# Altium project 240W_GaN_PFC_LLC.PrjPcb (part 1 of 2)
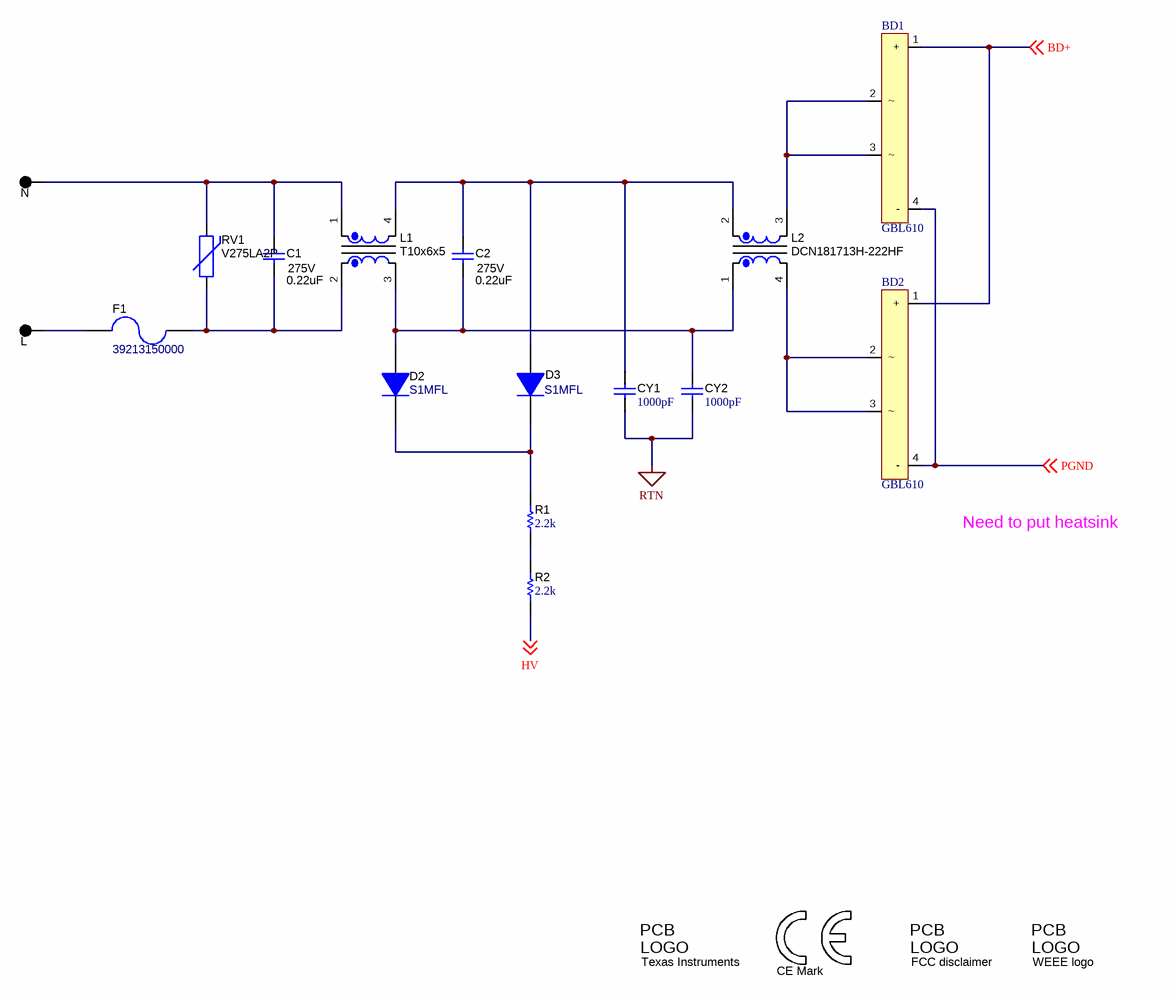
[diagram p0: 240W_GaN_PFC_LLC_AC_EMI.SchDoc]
CopyrightYear: 2024; PCB_Layout: M. Huang; PCB_Rev: E1; PRJ_Engineer: M. Huang / J. Gomez; PRJ_Number: 240W PFC + LLC; PRJ_Title: 240W PFC + LLC; SCH_Rev: E1; TechSupport: http://www.ti.com/support; TID: N/A
3 sheets, 163 parts. Net scope: global (net labels, ports and power ports of the same name join across sheets).
Board file: 240W_GaN_PFC_LLC.PcbDoc
Sheets:
  240W_GaN_PFC_LLC_AC_EMI.SchDoc
  240W_LLC_Stage.SchDoc
  240W_PFC_Stage.SchDoc

## Sheet 240W_GaN_PFC_LLC_AC_EMI.SchDoc
size 431 x 279 mm; Date: Not shown in title block; ApprovedBy: Not shown in title block; CheckedBy: Not shown in title block; Author: Not shown in title block; CompanyName: Not shown in title block; Engineer: Not shown in title block; Organization: Not shown in title block; Address1: Not shown in title block; Address2: Not shown in title block; Address3: Not shown in title block; Address4: Not shown in title block; DocumentNumber: 3; Revision: Use project parameter SCH_Rev; SheetNumber: 1; SheetTotal: 2; PageSetup: Record=PageOptions¦CenterHorizontal=True¦CenterVertical=True¦PrintScale=1.00¦XCorrection=1.00¦YCorrection=1.00¦PrintKind=0¦BorderSize=5000000¦LeftOffset=0¦BottomOffset=0¦Orientation=2¦PaperLength=1000¦PaperWidth=1000¦Scale=100¦PaperSource=15¦PrintQuality=600¦MediaType=1¦DitherType=10¦PaperKind=Letter¦PrintScaleMode=1

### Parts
BD1  GBL610  [GBL610]
BD2  GBL610  [GBL610]
C1  VDC_V: 275V  ValueDisplayed: 0.22uF  [WCAP-FTX2_1500x700x1250]  (hidden comment: 890324024002)
C2  VDC_V: 275V  ValueDisplayed: 0.22uF  [WCAP-FTX2_1500x700x1250]  (hidden comment: 890324024002)
CY1  ValueDisplayed: 1000pF  [DK1_86]  (hidden comment: DK1E3EA102M86RAH01)
CY2  ValueDisplayed: 1000pF  [DK1_86]  (hidden comment: DK1E3EA102M86RAH01)
D2  S1MFL  [SOD-123]
D3  S1MFL  [SOD-123]
F1  39213150000  [FUSE_392]
L1  T10x6x5  [T10x6x5]
L2  DCN181713H-222HF  [CM_DCN181713H]
Logo1  CE Mark  [CE_Mark_5mm]  (no BOM)
Logo2  Texas Instruments  [TI_Stacked_Overlay_Small]  (no BOM)
Logo3  FCC disclaimer  [FCC_disclaimer]  (no BOM)
Logo4  WEEE logo  [WEEE_Minimum]  (no BOM)
R1  ValueDisplayed: 2.2k  [1206]  (hidden comment: CRCW12062K20JNEA)
R2  ValueDisplayed: 2.2k  [1206]  (hidden comment: CRCW12062K20JNEA)
RV1  V275LA2P  [Littelfuse_V275LA_7MM]
TP1  N  [Keystone5011]
TP2  L  [Keystone5011]

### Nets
PGND: BD1.4(-) BD2.4(-) ; off-sheet PGND
RTN: CY1.2 CY2.2
BD+: BD1.1(+) BD2.1(+) ; off-sheet BD+
HV: R2.1 ; off-sheet HV
NetBD1_2: BD1.2 BD1.3 L2.3
NetBD2_2: BD2.2 BD2.3 L2.4
NetC1_1: C1.1 L1.1 RV1.2 TP1.1
NetC1_2: C1.2 F1.1 L1.2 RV1.1
NetC2_1: C2.1 CY1.1 D3.2(A) L1.4 L2.2
NetC2_2: C2.2 CY2.1 D2.2(A) L1.3 L2.1
NetD2_1: D2.1(K) D3.1(K) R1.2
NetF1_2: F1.2 TP2.1
NetR1_1: R1.1 R2.2

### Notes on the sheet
- Need to put heatsink

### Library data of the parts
BD1 BD2 = BD
C1 C2 = CMP-0012312-3: CAP, Film, 0.22 uF, 275 V, +/- 10%, TH; Manufacturer: Wurth Elektronik; TaMin_C: -40°C; Polarized: N; SizeAreaWB_mm2: 153; Value1: Unknown; Value: 0.22uF; TaMax_C: 105°C; SizeZ_mm: 13; SizeX_mm: 15; SizeY_mm: 7; Cap_Case: 15x7x12.5; SizeArea_mm2: 105; Cap_F: 220nF; AEC Category: Q200
CY1 CY2 = CMP-0077997-1: CAP, CERM, 1000 pF, X1 440 VAC/Y1 250 VAC, +/- 20%, E, 8x6mm; Manufacturer: MuRata; Cap_F: 1nF; VAC_X: 440; SizeAreaWB_mm2: 107.2; VAC_Y: 250; SizeArea_mm2: 68.4; AEC Qualified: N; AEC Category: Q200; Value: 1000pF; TaMax_C: 125°C; SizeZ_mm: 2.5; TaMin_C: -40°C; SizeY_mm: 6; U/M: EA; AC_Safety: X1Y1; SizeX_mm: 11.4
D2 D3 = CMP-0029032-2: Diode, GP, 1KV, 1 A, SOD-123F; Manufacturer: ON Semiconductor; Value: 1000V; Type: Switching; SizeY_mm: 1.7; Io_A: 1A; SizeAreaWB_mm2: 13.095; SizeArea_mm2: 6.545; Vf_V: 1V; TJmax_C: 150°C; SizeX_mm: 3.85; SizeZ_mm: 1.35; Green_Lifecycle: Active; Green_REACh: Passed
F1 = CMP-0003561-2: Fuse, 3.15 A, 250VAC/VDC, TH; Manufacturer: Littelfuse; Irating_A: 3.15A; VAC_V: 250V
L1 L2 = CM_Choke_Planar: Manufacturer: Used in BOM report; CompType: Used in some BOM reports.  Useful for finding later.
Logo1 = CMP-0074844-1: SymbolCreator: a0412235
Logo2 = CMP-0074838-1: Texas Instrument Corporate Signature; SymbolCreator: a0412235; Lib Reference: TI_Logo; Library Reference: Logo
Logo3 = CMP-0074847-1: FCC_disclaimer; Library Reference: Logo
Logo4 = CMP-0074769-1
R1 R2 = CMP-0018641-3: RES, 2.2 k, 5%, 0.25 W, AEC-Q200 Grade 0, 1206; Manufacturer: Vishay-Dale; Power_W: 250mW; TempCo: 200 ppm/C; Value_Code: 2k20; Value: 2.2k; EIA_Code: E24; SizeX_mm: 3.2; SizeY_mm: 1.6; SizeZ_mm: 1.35; Value2: 0.25W; SizeArea_mm2: 5.12; AEC Qualified: Y; VDC_V: 200V; AEC Category: Q200; AEC Grade: 0
RV1 = CMP-0001908-4: VARISTOR 450V 1.2KA DISC 7MM; Manufacturer: Littelfuse; SizeX_mm: 7; SizeArea_mm2: 39.2; SizeY_mm: 5.6; SizeAreaWB_mm2: 68.4; SizeZ_mm: 12
TP1 TP2 = CMP-0055148-1: Test Point, Multipurpose, Black, TH; Manufacturer: Keystone; CNHeader: FALSE; Green_Lifecycle: Active; Green_REACh: Passed; ContactFinish: Silver; CT: TRUE

## Sheet 240W_LLC_Stage.SchDoc
size 431 x 279 mm; Date: Not shown in title block; ApprovedBy: Not shown in title block; CheckedBy: Not shown in title block; Author: Not shown in title block; CompanyName: Not shown in title block; Engineer: Not shown in title block; Organization: Not shown in title block; Address1: Not shown in title block; Address2: Not shown in title block; Address3: Not shown in title block; Address4: Not shown in title block; DocumentNumber: 2; Revision: Use project parameter SCH_Rev; SheetNumber: 2; SheetTotal: 3; PageSetup: Record=PageOptions¦CenterHorizontal=True¦CenterVertical=True¦PrintScale=1.00¦XCorrection=1.00¦YCorrection=1.00¦PrintKind=0¦BorderSize=5000000¦LeftOffset=0¦BottomOffset=0¦Orientation=2¦PaperLength=1000¦PaperWidth=1000¦Scale=100¦PaperSource=15¦PrintQuality=600¦MediaType=1¦DitherType=10¦PaperKind=Letter¦PrintScaleMode=1
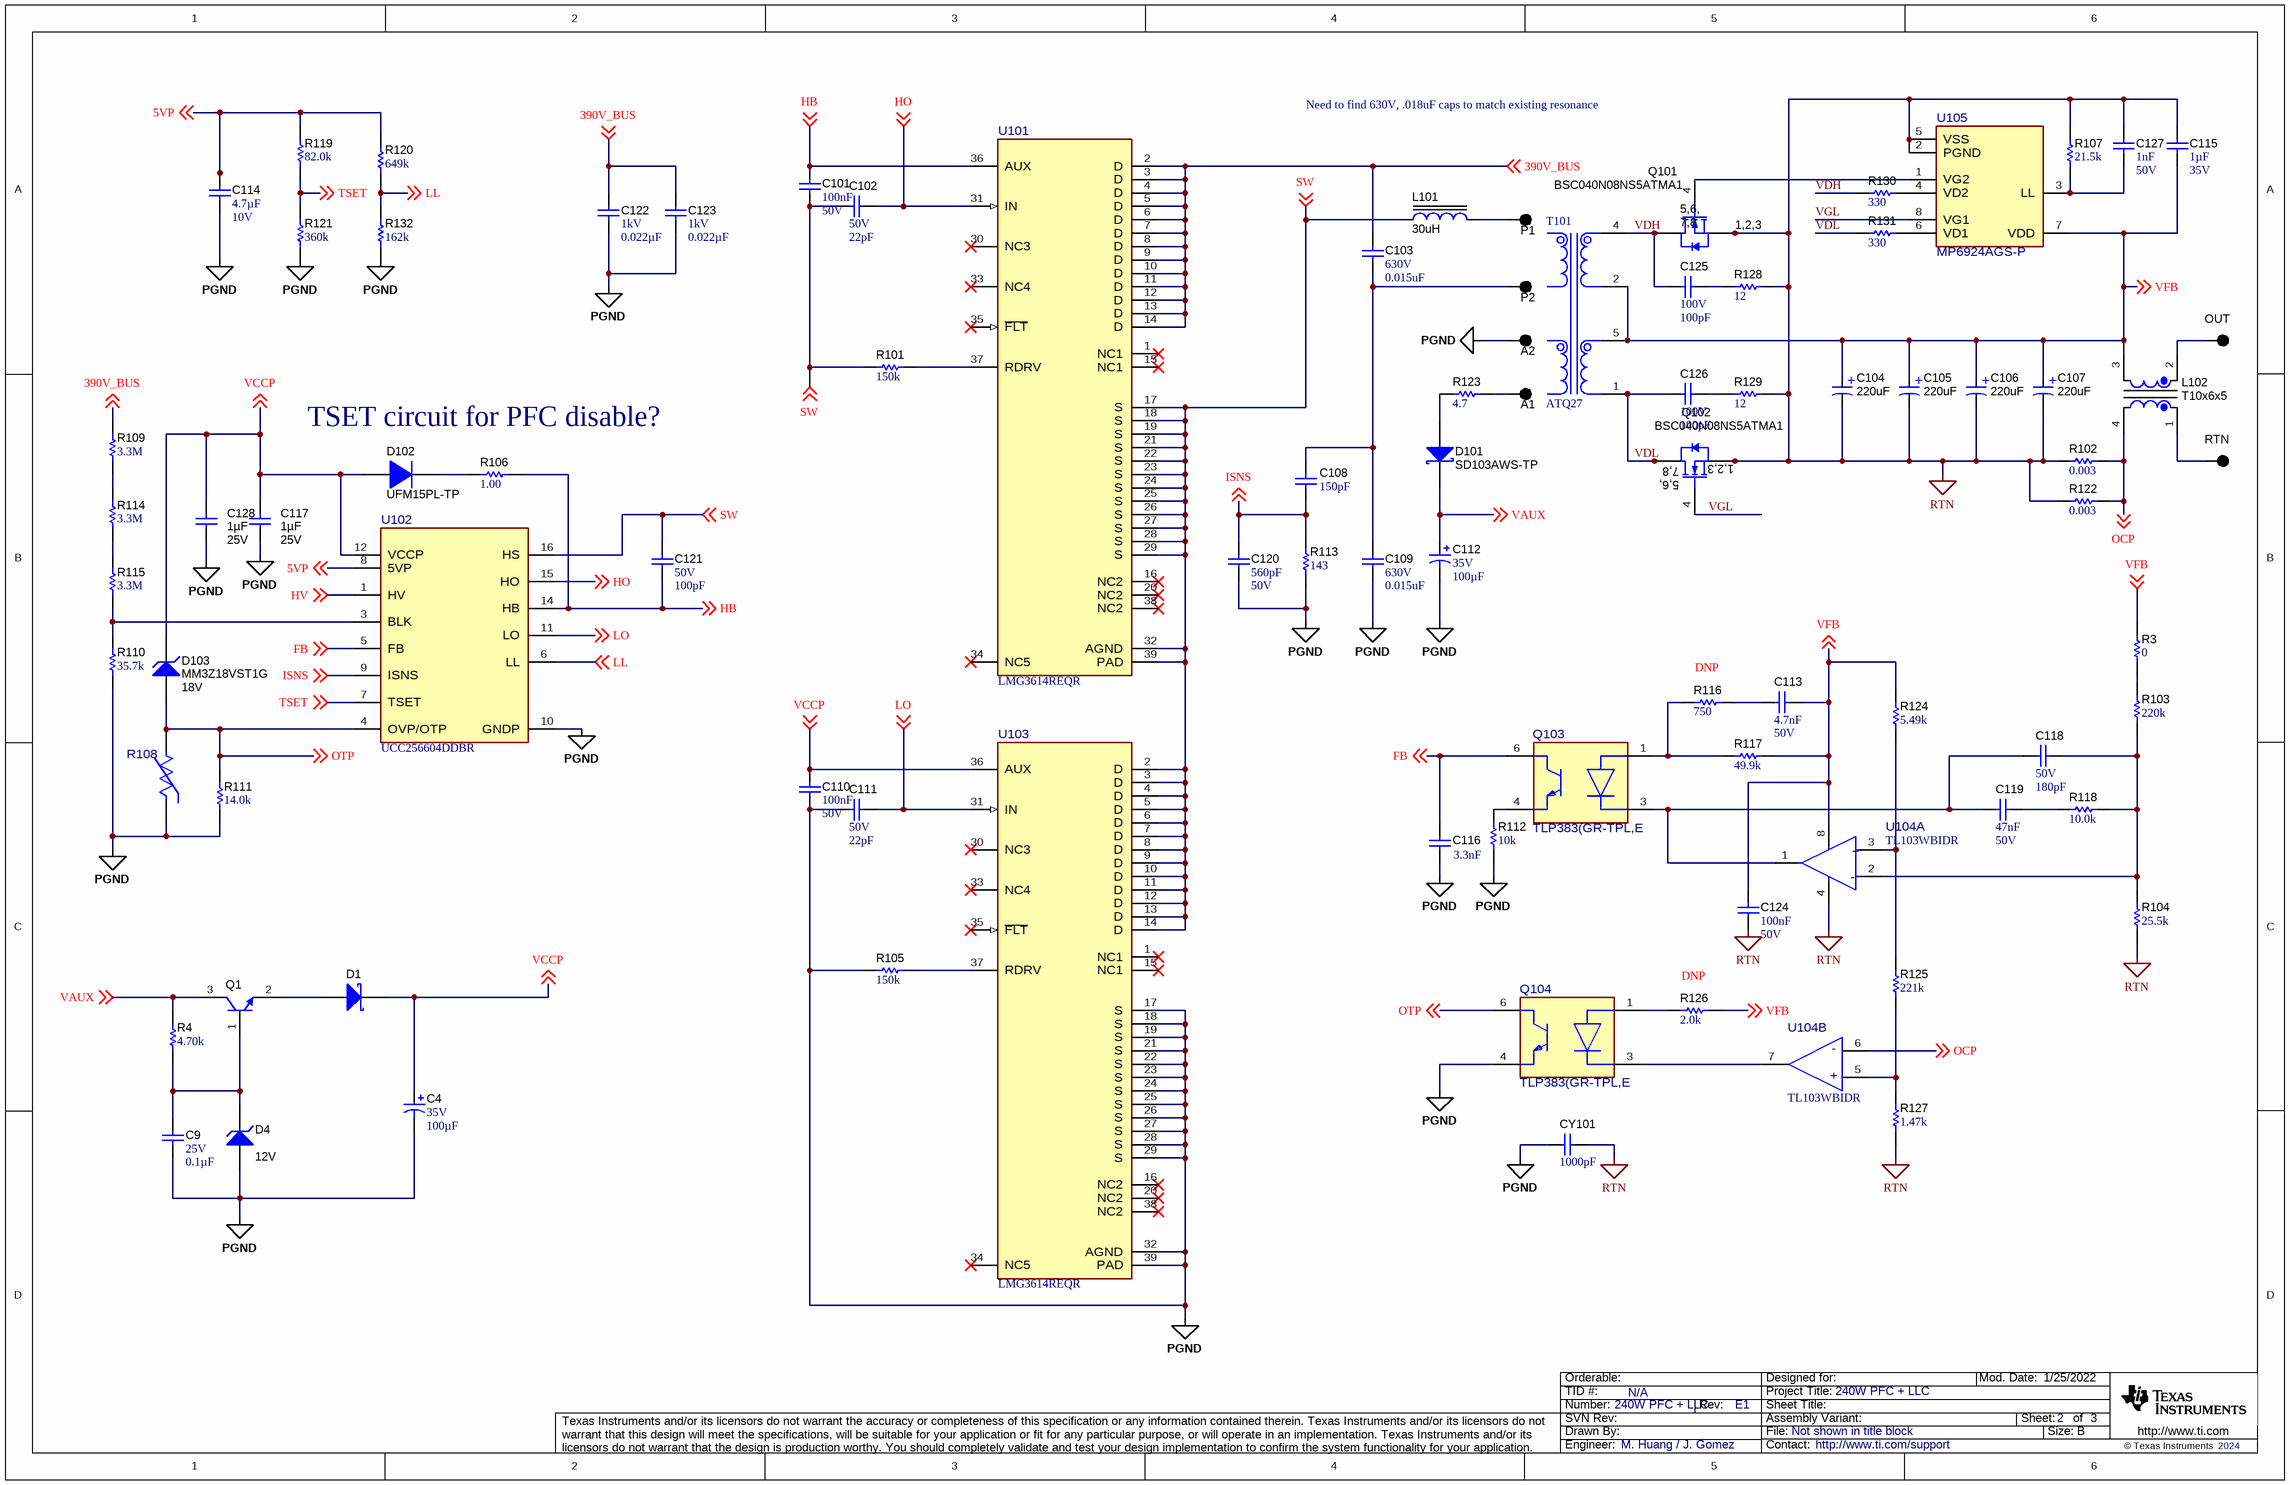
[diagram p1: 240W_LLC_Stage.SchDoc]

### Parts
C4  VDC_V: 35V  ValueDisplayed: 100µF  [Rubycon_630x1100]  (hidden comment: 35ZLJ100M6.3X11)
C9  VDC_V: 25V  ValueDisplayed: 0.1µF  [0402]  (hidden comment: CGA2B3X7R1E104K050BB)
C101  Cap_F: 100nF  VDC_V: 50V  [0603]  (hidden comment: 06035C104KAZ2A)
C102  VDC_V: 50V  ValueDisplayed: 22pF  [0603_HV]  (hidden comment: CGA3E2C0G1H220J080AA)
C103  VDC_V: 630V  ValueDisplayed: 0.015uF  [PHE426_1300x400x900]  (hidden comment: PHE426MA5150JR05)
C104  220uF  [Cap_8_P3.5_V]
C105  220uF  [Cap_8_P3.5_V]
C106  220uF  [Cap_8_P3.5_V]
C107  220uF  [Cap_8_P3.5_V]
C108  ValueDisplayed: 150pF  [1206]  (hidden comment: GRM31A5C2J151JW01D)
C109  VDC_V: 630V  ValueDisplayed: 0.015uF  [PHE426_1300x400x900]  (hidden comment: PHE426MA5150JR05)
C110  Cap_F: 100nF  VDC_V: 50V  [0603]  (hidden comment: 06035C104KAZ2A)
C111  VDC_V: 50V  ValueDisplayed: 22pF  [0603_HV]  (hidden comment: CGA3E2C0G1H220J080AA)
C112  VDC_V: 35V  ValueDisplayed: 100µF  [Rubycon_630x1100]  (hidden comment: 35ZLJ100M6.3X11)
C113  Cap_F: 4.7nF  VDC_V: 50V  [0603_HV]  (hidden comment: C0603C472K5RACTU)
C114  Cap_F: 4.7µF  VDC_V: 10V  [0603_HV]  (hidden comment: GRM188Z71A475ME15D)
C115  Cap_F: 1µF  VDC_V: 35V  [0603]  (hidden comment: C1608X7R1V105K080AC)
C116  Cap_F: 3.3nF  [0603_HV]  (hidden comment: C0603C332F5GACTU)
C117  Cap_F: 1µF  VDC_V: 25V  [0603_HV]  (hidden comment: GRJ188R71E105KE11D)
C118  VDC_V: 50V  ValueDisplayed: 180pF  [0603]  (hidden comment: GRM1885C1H181JA01D)
C119  Cap_F: 47nF  VDC_V: 50V  [0603]  (hidden comment: C1608X7R1H473K080AA)
C120  Cap_F: 560pF  VDC_V: 50V  [0603]  (hidden comment: C0603C561K5RACTU)
C121  VDC_V: 50V  ValueDisplayed: 100pF  [0603]  (hidden comment: C0603C101F5GACTU)
C122  VDC_V: 1kV  ValueDisplayed: 0.022µF  [1206_190]  (hidden comment: C1206C223KDRACTU)
C123  VDC_V: 1kV  ValueDisplayed: 0.022µF  [1206_190]  (hidden comment: C1206C223KDRACTU)
C124  Cap_F: 100nF  VDC_V: 50V  [0603_HV]  (hidden comment: C0603C104K5RACTU)
C125  VDC_V: 100V  ValueDisplayed: 100pF  [0603]  (hidden comment: C1608C0G2A101F080AA)
C126  VDC_V: 100V  ValueDisplayed: 100pF  [0603]  (hidden comment: C1608C0G2A101F080AA)
C127  Cap_F: 1nF  VDC_V: 50V  [0603_HV]  (hidden comment: C0603X102K5RACTU)
C128  Cap_F: 1µF  VDC_V: 25V  [0603_HV]  (hidden comment: GRJ188R71E105KE11D)
CY101  ValueDisplayed: 1000pF  [DK1_86]  (hidden comment: DK1E3EA102M86RAH01)
D1  CD0603-B0130L  [Diode_0603]  (value not drawn)
D4  value 12V  [SOD-323]  (hidden comment: MMSZ5242BS-7-F)
D101  SD103AWS-TP  [SOD-323]
D102  UFM15PL-TP  [SOD-123FL]
D103  MM3Z18VST1G  value 18V  [SOD-323]
L101  30uH  [ATQ18]
L102  T10x6x5  [T10x6x5]
Q1  MMBT3904-7-F  [SOT-23]  (value not drawn)
Q101  BSC040N08NS5ATMA1  [PG-TDSON-8]
Q102  BSC040N08NS5ATMA1  [PG-TDSON-8]
Q103  TLP383(GR-TPL,E  [FP-TLP383(GR-TPL,E_SO6-4-MFG]
Q104  TLP383(GR-TPL,E  [FP-TLP383(GR-TPL,E_SO6-4-MFG]
R3  ValueDisplayed: 0  [0603]  (hidden comment: RC0603JR-070RL)
R4  ValueDisplayed: 4.70k  [0402]  (hidden comment: CRG0402F4K7)
R101  ValueDisplayed: 150k  [0603_HV]  (hidden comment: CRCW0603150KJNEA)
R102  ValueDisplayed: 0.003  [1206]  (hidden comment: CSNL1206FT3L00)
R103  ValueDisplayed: 220k  [0603_HV]  (hidden comment: RC0603FR-07220KL)
R104  ValueDisplayed: 25.5k  [0603_HV]  (hidden comment: RC0603FR-0725K5L)
R105  ValueDisplayed: 150k  [0603_HV]  (hidden comment: CRCW0603150KJNEA)
R106  ValueDisplayed: 1.00  [0603_HV]  (hidden comment: RC0603FR-071RL)
R107  ValueDisplayed: 21.5k  [0603_HV]  (hidden comment: RC0603FR-0721K5L)
R108  B57371V2474J060  [FP-B57371V2474J060_0603-MFG]  (value not drawn)
R109  ValueDisplayed: 3.3M  [0805_HV]  (hidden comment: ERJ-6GEYJ335V)
R110  ValueDisplayed: 35.7k  [0603_HV]  (hidden comment: RC0603FR-0735K7L)
R111  ValueDisplayed: 14.0k  [0603_HV]  (hidden comment: RC0603FR-0714KL)
R112  ValueDisplayed: 10k  [0603_HV]  (hidden comment: RC0603JR-0710KL)
R113  ValueDisplayed: 143  [0603]  (hidden comment: CRCW0603143RFKEA)
R114  ValueDisplayed: 3.3M  [0805_HV]  (hidden comment: ERJ-6GEYJ335V)
R115  ValueDisplayed: 3.3M  [0805_HV]  (hidden comment: ERJ-6GEYJ335V)
R116  ValueDisplayed: 750  [0603_HV]  (hidden comment: CRCW0603750RFKEA)
R117  ValueDisplayed: 49.9k  [0603]  (hidden comment: RC0603FR-0749K9L)
R118  ValueDisplayed: 10.0k  [0603]  (hidden comment: M55342K12B10E0T)
R119  ValueDisplayed: 82.0k  [0603]  (hidden comment: RC0603FR-0782KL)
R120  ValueDisplayed: 649k  [0603_HV]  (hidden comment: RC0603FR-07649KL)
R121  ValueDisplayed: 360k  [0603]  (hidden comment: RC0603FR-07360KL)
R122  ValueDisplayed: 0.003  [1206]  (hidden comment: CSNL1206FT3L00)
R123  ValueDisplayed: 4.7  [0603_HV]  (hidden comment: CRCW06034R70JNEA)
R124  ValueDisplayed: 5.49k  [0603]  (hidden comment: RC0603FR-075K49L)
R125  ValueDisplayed: 221k  [0603_HV]  (hidden comment: RC0603FR-07221KL)
R126  ValueDisplayed: 2.0k  [0603_HV]  (hidden comment: CRCW06032K00JNEA)
R127  ValueDisplayed: 1.47k  [0603_HV]  (hidden comment: RC0603FR-071K47L)
R128  ValueDisplayed: 12  [0603_HV]  (hidden comment: CRCW060312R0JNEA)
R129  ValueDisplayed: 12  [0603_HV]  (hidden comment: CRCW060312R0JNEA)
R130  ValueDisplayed: 330  [0603_HV]  (hidden comment: RC0603JR-07330RL)
R131  ValueDisplayed: 330  [0603_HV]  (hidden comment: RC0603JR-07330RL)
R132  ValueDisplayed: 162k  [0603_HV]  (hidden comment: RC0603FR-07162KL)
T101  ATQ27  [ATQ27]
TP101  OUT  [Keystone5011]
TP102  P1  [Keystone5011]
TP103  P2  [Keystone5011]
TP104  A2  [Keystone5011]
TP105  A1  [Keystone5011]
TP106  RTN  [Keystone5011]
U101  LMG3614REQR  [REQ0038A-MFG]
U102  UCC256604DDBR  [DDB0014A-MFG]
U103  LMG3614REQR  [REQ0038A-MFG]
U104  TL103WBIDR  [D0008A-MFG]  (parts A,B of 2)
U105  MP6924AGS-P  [FP-MP6924AGS-P_SOIC8-MFG]

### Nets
PGND: C4.2(-) C9.2 C109.2 C110.2 C111.2 C112.2(-) C114.2 C116.2 C117.1 C120.2 C122.2 C123.2 C128.1 CY101.2 D4.2(A) Q104.4(Emitter) R105.1 R108.1 R110.1 R111.1 R112.1 R113.1 R121.1 R132.1 TP104.1 U102.10(GNDP) U103.17(S) U103.18(S) U103.19(S) U103.21(S) U103.22(S) U103.23(S) U103.24(S) U103.25(S) U103.26(S) U103.27(S) U103.28(S) U103.29(S) U103.32(AGND) U103.39(PAD)
RTN: C104.2(N) C105.2(N) C106.2(N) C107.2(N) C115.2 C124.2 C127.1 CY101.1 Q101.1(S) Q101.2(S) Q101.3(S) Q102.1(S) Q102.2(S) Q102.3(S) R102.1 R104.1 R107.1 R122.1 R127.1 R128.2 R129.2 U104.4(VCC-) U105.2(PGND) U105.5(VSS)
5VP: C114.1 R119.2 R120.2 U102.8(5VP) ; off-sheet 5VP
390V_BUS: C103.1 C122.1 C123.1 R109.1 U101.2(D) U101.3(D) U101.4(D) U101.5(D) U101.6(D) U101.7(D) U101.8(D) U101.9(D) U101.10(D) U101.11(D) U101.12(D) U101.13(D) U101.14(D) ; off-sheet 390V_BUS
FB: C116.1 Q103.6(Collector) U102.5(FB) ; off-sheet FB
HB: C101.1 C121.2 R106.2 U101.36(AUX) U102.14(HB) ; off-sheet HB
HO: C102.1 U101.31(IN) U102.15(HO) ; off-sheet HO
HV: U102.1(HV) ; off-sheet HV
ISNS: C108.2 C120.1 R113.2 U102.9(ISNS) ; off-sheet ISNS
LL: R120.1 R132.2 U102.6(LL) ; off-sheet LL
LO: C111.1 U102.11(LO) U103.31(IN) ; off-sheet LO
OCP: L102.4 R102.2 R122.2 U104.6(2IN-) ; off-sheet OCP
OTP: D103.2(A) Q104.6(Collector) R108.2 R111.2 U102.4(OVP/OTP) ; off-sheet OTP
SW: C101.2 C102.2 C121.1 L101.1 R101.1 U101.17(S) U101.18(S) U101.19(S) U101.21(S) U101.22(S) U101.23(S) U101.24(S) U101.25(S) U101.26(S) U101.27(S) U101.28(S) U101.29(S) U101.32(AGND) U101.39(PAD) U102.16(HS) U103.2(D) U103.3(D) U103.4(D) U103.5(D) U103.6(D) U103.7(D) U103.8(D) U103.9(D) U103.10(D) U103.11(D) U103.12(D) U103.13(D) U103.14(D) ; off-sheet SW
TSET: R119.1 R121.2 U102.7(TSET) ; off-sheet TSET
VAUX: C112.1(+) D101.1(K) Q1.3(C) R4.2 ; off-sheet VAUX
VCCP: C4.1(+) C110.1 C117.2 C128.2 D1.1(K) D102.2(A) D103.1(K) U102.12(VCCP) U103.36(AUX) ; off-sheet VCCP
VDH: C125.2 Q101.5(D) Q101.6(D) Q101.7(D) Q101.8(D) Q101.9(D) R130.1 T101.4
VDL: C126.2 Q102.5(D) Q102.6(D) Q102.7(D) Q102.8(D) Q102.9(D) R131.1 T101.1
VFB: C104.1(P) C105.1(P) C106.1(P) C107.1(P) C113.1 C115.1 C124.1 L102.3 R3.2 R117.2 R124.2 R126.1 T101.2 T101.5 U104.8(VCC+) U105.7(VDD) ; off-sheet VFB
VGL: Q102.4(G) U105.8(VG1)
NetC9_1: C9.1 D4.1(K) Q1.1(B) R4.1
NetC103_2: C103.2 C108.1 C109.1 TP103.1
NetC113_2: C113.2 R116.2
NetC118_1: C118.1 R103.1 R104.2 R118.2 U104.2(1IN-)
NetC118_2: C118.2 C119.2 Q103.3(Cathode) U104.1(1OUT)
NetC119_1: C119.1 R118.1
NetC125_1: C125.1 R128.1
NetC126_1: C126.1 R129.1
NetC127_2: C127.2 R107.2 U105.3(LL)
NetD1_2: D1.2(A) Q1.2(E)
NetD101_2: D101.2(A) R123.1
NetD102_1: D102.1(K) R106.1
NetL101_4: L101.4 TP102.1
NetL102_1: L102.1 TP106.1
NetL102_2: L102.2 TP101.1
NetQ101_4: Q101.4(G) U105.1(VG2)
NetQ103_1: Q103.1(Anode) R116.1 R117.1
NetQ103_4: Q103.4(Emitter) R112.2
NetQ104_1: Q104.1(Anode) R126.2
NetQ104_3: Q104.3(Cathode) U104.7(2OUT)
NetR3_1: R3.1 R103.2
NetR101_2: R101.2 U101.37(RDRV)
NetR105_2: R105.2 U103.37(RDRV)
NetR109_2: R109.2 R114.2
NetR110_2: R110.2 R115.1 U102.3(BLK)
NetR114_1: R114.1 R115.2
NetR123_2: R123.2 TP105.1
NetR124_1: R124.1 R125.2 U104.3(1IN+)
NetR125_1: R125.1 R127.2 U104.5(2IN+)
NetR130_2: R130.2 U105.4(VD2)
NetR131_2: R131.2 U105.6(VD1)

Not connected (* = marked no-connect by the designer): U101 1(NC1)* 15(NC1)* 16(NC2)* 20(NC2)* 30(NC3)* 33(NC4)* 34(NC5)* 35(~{FLT})* 38(NC2)*; U103 1(NC1)* 15(NC1)* 16(NC2)* 20(NC2)* 30(NC3)* 33(NC4)* 34(NC5)* 35(~{FLT})* 38(NC2)*

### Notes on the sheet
- Need to find 630V, .018uF caps to match existing resonance
- TSET circuit for PFC disable?
- (near R116) DNP
- (near R126) DNP

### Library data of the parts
C4 C112 = CMP-0080807-1: CAP, AL, 100 µF, 35 V, +/- 20%, TH; Manufacturer: Rubycon; IRMS_A: 700mA; SizeAreaWB_mm2: 68.89; SizeArea_mm2: 39.69; AEC Qualified: N; AEC Category: Q200; Value: 100uF; TaMax_C: 105°C; SizeZ_mm: 12.5; Polarized: Y; TaMin_C: -40°C; SizeY_mm: 6.3; U/M: EA; CompType: Capacitor; Cap_Case: 6.3x11
C9 = CMP-0080610-1: CAP, CERM, 0.1 µF, 25 V,+/- 10%, X7R, AEC-Q200 Grade 1, 0402; Manufacturer: TDK; TaMin_C: -55°C; Polarized: N; SizeAreaWB_mm2: 3; U/M: EA; Value: 0.1uF; TaMax_C: 125°C; SizeZ_mm: 0.6; SizeX_mm: 1; SizeY_mm: 0.5; AEC Qualified: Y; Cap_F: 100nF; AEC Category: Q200
C101 C110 = CMP-0079095-1: CAP, CERM, 0.1 µF, 50 V,+/- 10%, X7R, AEC-Q200 Grade 1, 0603; Manufacturer: AVX; SizeAreaWB_mm2: 4.68; SizeArea_mm2: 1.28; AEC Qualified: Y; AEC Category: Q200; Value: 0.1uF; TaMax_C: 125°C; SizeZ_mm: 1; Polarized: N; TaMin_C: -55°C; SizeY_mm: 0.8; U/M: EA; SizeX_mm: 1.6; ValueDisplayed: 0.1µF
C102 C111 = CMP-0007071-4: CAP, CERM, 22 pF, 50 V, +/- 5%, C0G/NP0, AEC-Q200 Grade 1, 0603; Manufacturer: TDK; TaMin_C: -55°C; Polarized: N; SizeAreaWB_mm2: 4.68; Value1: Unknown; U/M: EA; Value: 22pF; TaMax_C: 125°C; SizeZ_mm: 1; SizeX_mm: 1.6; SizeY_mm: 0.8; Cap_Case: 0603; SizeArea_mm2: 1.28; AEC Qualified: Y; AEC Category: Q200
C103 C109 = CMP-0012541-3: CAP, Film, 0.015 uF, 630 V, +/- 20%, TH; Manufacturer: Kemet; TaMin_C: -55°C; Polarized: N; SizeAreaWB_mm2: 90; Value1: Unknown; TaMax_C: 105°C; SizeZ_mm: 9; SizeX_mm: 13; SizeY_mm: 4; Cap_Case: 13x4x9mm; SizeArea_mm2: 52; Cap_F: 15nF; AEC Category: Q200
C104-C107 = E-Cap: 227AVG035MFBJ; Manufacturer: Used in BOM report; CompType: Used in some BOM reports.  Useful for finding later.
C108 = CMP-0008885-2: CAP, CERM, 150 pF, 630 V, +/- 5%, C0G/NP0, 1206; Manufacturer: MuRata; TaMin_C: -55°C; Polarized: N; SizeAreaWB_mm2: 10.92; Value1: Unknown; U/M: EA; Value: 150pF; TaMax_C: 125°C; SizeZ_mm: 1.35; SizeX_mm: 3.2; SizeY_mm: 1.6; Value2: 630V; SizeArea_mm2: 5.12; AEC Category: Q200
C113 = CMP-0006943-4: CAP, CERM, 4700 pF, 50 V, +/- 10%, X7R, 0603; Manufacturer: Kemet; TaMin_C: -55°C; Polarized: N; SizeAreaWB_mm2: 4.68; Value1: Unknown; U/M: EA; Value: 4700pF; TaMax_C: 125°C; SizeZ_mm: 1; SizeX_mm: 1.6; SizeY_mm: 0.8; Cap_Case: 0603; SizeArea_mm2: 1.28; AEC Category: Q200
C114 = CMP-0007498-4: CAP, CERM, 4.7 uF, 10 V, +/- 20%, X7R, 0603; Manufacturer: MuRata; TaMin_C: -55°C; Polarized: N; SizeAreaWB_mm2: 4.68; Value1: Unknown; U/M: EA; Value: 4.7uF; TaMax_C: 125°C; SizeZ_mm: 1; SizeX_mm: 1.6; SizeY_mm: 0.8; Cap_Case: 0603; SizeArea_mm2: 1.28; AEC Category: Q200
C115 = CMP-0007052-4: CAP, CERM, 1 uF, 35 V, +/- 10%, X7R, 0603; Manufacturer: TDK; TaMin_C: -55°C; Polarized: N; SizeAreaWB_mm2: 4.68; Value1: Unknown; U/M: EA; Value: 1uF; TaMax_C: 125°C; SizeZ_mm: 1; SizeX_mm: 1.6; SizeY_mm: 0.8; SizeArea_mm2: 1.28; AEC Category: Q200
C116 = CMP-0081060-1: CAP, CERM, 3300 pF, 50 V,+/- 1%, C0G/NP0, 0603; Manufacturer: Kemet; TaMin_C: -55°C; Polarized: N; Green_Lifecycle: Active; SizeAreaWB_mm2: 4.68; Green_REACh: Passed; U/M: EA; Value: 3300pF; TaMax_C: 125°C; SizeZ_mm: 1; SizeX_mm: 1.6; SizeY_mm: 0.8; Cap_Case: 0603; Value2: 50V; SizeArea_mm2: 1.28; AEC Category: Q200
C117 C128 = CMP-0079720-1: CAP, CERM, 1 µF, 25 V,+/- 10%, X7R, 0603; Manufacturer: MuRata; TaMin_C: -55°C; Polarized: N; SizeAreaWB_mm2: 4.68; U/M: EA; Value: 1uF; TaMax_C: 125°C; SizeZ_mm: 1; SizeX_mm: 1.6; SizeY_mm: 0.8; Cap_Case: 0603; SizeArea_mm2: 1.28; AEC Category: Q200
C118 = CMP-0007191-4: CAP, CERM, 180 pF, 50 V, +/- 5%, C0G/NP0, 0603; Manufacturer: MuRata; TaMin_C: -55°C; Polarized: N; SizeAreaWB_mm2: 4.68; Value1: Unknown; U/M: EA; Value: 180pF; TaMax_C: 125°C; SizeZ_mm: 1; SizeX_mm: 1.6; SizeY_mm: 0.8; SizeArea_mm2: 1.28; AEC Category: Q200
C119 = CMP-0007049-4: CAP, CERM, 0.047 uF, 50 V, +/- 10%, X7R, 0603; Manufacturer: TDK; TaMin_C: -55°C; ESR_ohm: 49.007m; Polarized: N; SizeAreaWB_mm2: 4.68; Value1: 0.049007 ohm; U/M: EA; TaMax_C: 125°C; SizeZ_mm: 1; SizeX_mm: 1.6; SizeY_mm: 0.8; SizeArea_mm2: 1.28; IRMS_A: 767.528mA; AEC Category: Q200
C120 = CMP-0006954-4: CAP, CERM, 560 pF, 50 V, +/- 10%, X7R, 0603; Manufacturer: Kemet; TaMin_C: -55°C; Polarized: N; SizeAreaWB_mm2: 4.68; Value1: Unknown; U/M: EA; Value: 560pF; TaMax_C: 125°C; SizeZ_mm: 1; SizeX_mm: 1.6; SizeY_mm: 0.8; SizeArea_mm2: 1.28; AEC Category: Q200
C121 = CMP-0080091-1: CAP, CERM, 100 pF, 50 V,+/- 1%, C0G/NP0, 0603; Manufacturer: Kemet; SizeAreaWB_mm2: 4.68; SizeArea_mm2: 1.28; AEC Qualified: N; AEC Category: Q200; Value: 100pF; TaMax_C: 125°C; SizeZ_mm: 1; Green_REACh: Passed; TaMin_C: -55°C; SizeY_mm: 0.8; Green_Lifecycle: Active; U/M: EA; SizeX_mm: 1.6
C122 C123 = CMP-0084048-1: CAP, CERM, 0.022 µF, 1000 V,+/- 10%, X7R, AEC-Q200 Grade 1, 1206; Manufacturer: Kemet; TaMin_C: -55°C; Polarized: N; SizeAreaWB_mm2: 10.92; U/M: EA; Value: 0.022uF; TaMax_C: 125°C; SizeZ_mm: 1.9; SizeX_mm: 3.2; SizeY_mm: 1.6; Cap_Case: 1206; Value2: 1000V; SizeArea_mm2: 5.12; AEC Qualified: Y; Cap_F: 22nF; AEC Grade: 1; AEC Category: Q200
C124 = CMP-0006861-4: CAP, CERM, 0.1 uF, 50 V, +/- 10%, X7R, 0603; Manufacturer: Kemet; TaMin_C: -55°C; Polarized: N; SizeAreaWB_mm2: 4.68; Value1: Unknown; U/M: EA; Value: 0.1uF; TaMax_C: 125°C; SizeZ_mm: 1; SizeX_mm: 1.6; SizeY_mm: 0.8; Cap_Case: 0603; SizeArea_mm2: 1.28; AEC Category: Q200
C125 C126 = CMP-0006992-4: CAP, CERM, 100 pF, 100 V, +/- 1%, C0G/NP0, 0603; Manufacturer: TDK; TaMin_C: -55°C; Polarized: N; SizeAreaWB_mm2: 4.68; Value1: Unknown; U/M: EA; Value: 100pF; TaMax_C: 125°C; SizeZ_mm: 1; SizeX_mm: 1.6; SizeY_mm: 0.8; SizeArea_mm2: 1.28; AEC Category: Q200
C127 = CMP-0006976-5: CAP, CERM, 1000 pF, 50 V, +/- 10%, X7R, 0603; Manufacturer: Kemet; TaMin_C: -55°C; Polarized: N; SizeAreaWB_mm2: 4.68; Value1: Unknown; U/M: EA; Value: 1000pF; TaMax_C: 125°C; SizeZ_mm: 1; SizeX_mm: 1.6; SizeY_mm: 0.8; Cap_Case: 0603; SizeArea_mm2: 1.28; AEC Category: Q200
CY101 = CMP-0077997-1: as CY1 on sheet 240W_GaN_PFC_LLC_AC_EMI
D1 = CMP-0028466-3: Diode, Schottky, 35 V, 0.1 A, 0603 Diode; Manufacturer: Bourns; MFG_Status: TI_Obsolete; SizeY_mm: 0.9; SizeArea_mm2: 1.53; SizeX_mm: 1.7; Vr_V: 35V; Value: 35V; Green_REACh: Incomplete; Value2: 0.44V; TJmax_C: 125°C; Io_A: 100mA; SizeAreaWB_mm2: 5.13; SizeZ_mm: 0.75; Value1: 0.1A; Green_Lifecycle: Not Set; AEC Category: Q101; Vf_V: 440mV
D4 = CMP-0005831-4: Diode, Zener, 12 V, 200 mW, SOD-323; Manufacturer: Diodes Inc.; Power_W: 200mW; SizeZ_mm: 1; SizeX_mm: 2.7; SizeAreaWB_mm2: 8.695; Value1: 0.2W; RJA_CperW: 350; AEC Category: Q101; SizeArea_mm2: 3.645; SizeY_mm: 1.35
D101 = CMP-0076928-2: Diode, Schottky, 40 V, 0.35 A, SOD-323; Manufacturer: Micro Commercial Components; Value: 40V; SizeX_mm: 2.7; SizeAreaWB_mm2: 8.695; AEC Category: Q101; Vf_V: 600mV; SizeArea_mm2: 3.645; Green_Lifecycle: Not Set; SizeY_mm: 1.35; Io_A: 350mA; SizeZ_mm: 1.0; Green_REACh: Incomplete; Value2: 0.6V; Value1: 0.35A
D102 = CMP-0029148-2: Diode, Ultrafast, 600 V, 1 A, SOD-123FL; Manufacturer: Micro Commercial Components; SizeY_mm: 1.65; Value: 600V; Io_A: 1A; Green_Lifecycle: Not Set; Green_REACh: Incomplete; SizeX_mm: 3.6; SizeAreaWB_mm2: 12.19; SizeArea_mm2: 5.94; AEC Qualified: N; Value2: 1.7V; SizeZ_mm: 0.98; AEC Category: Q101; TJmax_C: 150°C
D103 = CMP-0085766-1: Diode, Zener, 18 V, 300 mW, SOD-323; Manufacturer: ON Semiconductor; SizeAreaWB_mm2: 8.695; SizeArea_mm2: 3.645; Power_W: 300mW; SizeX_mm: 2.7; SizeY_mm: 1.35; Value1: 0.3W; SizeZ_mm: 1; AEC Qualified: N; AEC Category: Q101; RJA_CperW: 416
L101 = L_FIX: Manufacturer: Used in BOM report; CompType: Used in some BOM reports.  Useful for finding later.
L102 = CM_Choke_Planar: as L1 on sheet 240W_GaN_PFC_LLC_AC_EMI
Q1 = CMP-0000387-2: Transistor, NPN, 40 V, 0.2 A, SOT-23; Manufacturer: Diodes Inc.; TaMax_C: 150°C; Value2: 400; Value1: 0.2 A; Vcesat1_V: 200mV; SizeX_mm: 2.5; SizeY_mm: 3; TaMin_C: -55°C; IcRated_A: 200mA; CompType: BJT; SizeZ_mm: 1.1; Value: 40 V; SizeArea_mm2: 7.5; NPN: 1; Vceo_V: 40V; PNP: 0; AEC Category: Q101; SizeAreaWB_mm2: 14; U/M: EA
Q101 Q102 = CMP-0000296-1: MOSFET, N-CH, 30 V, 100 A, PG-TDSON-8; PartNumber: BSC020N03MS G; Alternate Manufacturer: None; Manufacturer: Infineon Technologies; SizeZ_mm: 1.12; ChType: N; Value2: 45 nC; Value1: 0.002; VdsMax_V: 30V; SizeX_mm: 5.99; SizeY_mm: 4.9; Vgs_V: 20V; Value: 30V; Rdson45_ohm: 2.5m; SizeArea_mm2: 29.351; AEC Category: Q101; IdsMax_A: 100A; SizeAreaWB_mm2: 55.131; U/M: EA; QgTyp_nC: 45
Q103 Q104 = CMP-0087394-2: Optoisolator Transistor Output 5000Vrms 1 Channel 6-SO; Manufacturer: Toshiba; CTR (Max): 300%; CTR (Min): 100%; SizeZ_mm: 2.3mm
R3 = CMP-0025885-5: RES, 0, 5%, 0.1 W, 0603; Manufacturer: Yageo; Power_W: 100mW; TempCo: 200 ppm/C; Value_Code: 0000; Value: 0; EIA_Code: E24; SizeX_mm: 1.6; SizeZ_mm: 1; Value2: 0.1W; SizeArea_mm2: 1.28; AEC Qualified: N; VDC_V: 75V; AEC Category: Q200; SizeY_mm: 0.8; SizeAreaWB_mm2: 4.68
R4 = CMP-0026631-1: RES, 4.70 k, 1%, 0.063 W, 0402; Manufacturer: TE Connectivity; Power_W: 63mW; TempCo: 100 ppm/C; Value_Code: 4k70; U/M: EA; Value: 4.70k; Res_ohm: 4.7k; SizeX_mm: 1; SizeY_mm: 0.5; SizeZ_mm: 0.6; Value2: 0.063W; AEC Qualified: N; AEC Category: Q200
R101 R105 = CMP-0025717-4: RES, 150 k, 5%, 0.1 W, AEC-Q200 Grade 0, 0603; Manufacturer: Vishay-Dale; Power_W: 100mW; TempCo: 200 ppm/C; Value: 150k; EIA_Code: E24; SizeX_mm: 1.6; SizeY_mm: 0.8; SizeZ_mm: 1; Value2: 0.1W; SizeArea_mm2: 1.28; AEC Qualified: Y; VDC_V: 75V; AEC Category: Q200; AEC Grade: 0
R102 R122 = CMP-0017255-2: RES, 0.003, 1%, 1 W, 1206; Manufacturer: Stackpole Electronics Inc; Power_W: 1W; TempCo: 50 ppm/C; Value_Code: 3L000; U/M: EA; Value: 0.003; EIA_Code: E96; Res_ohm: 3m; SizeX_mm: 3.2; SizeY_mm: 1.6; SizeZ_mm: 1.35; SizeArea_mm2: 5.12; AEC Category: Q200
R103 = CMP-0022917-4: RES, 220 k, 1%, 0.1 W, 0603; Manufacturer: Yageo; Power_W: 100mW; TempCo: 100 ppm/C; Value: 220k; SizeX_mm: 1.6; SizeY_mm: 0.8; SizeZ_mm: 1; Value2: 0.1W; SizeArea_mm2: 1.28; AEC Qualified: N; VDC_V: 75V; AEC Category: Q200; SizeAreaWB_mm2: 4.68
R104 = CMP-0022951-5: RES, 25.5 k, 1%, 0.1 W, 0603; Manufacturer: Yageo; Power_W: 100mW; TempCo: 100 ppm/C; Value_Code: 25k5; Value: 25.5k; EIA_Code: E96; SizeX_mm: 1.6; SizeY_mm: 0.8; SizeZ_mm: 1; Value2: 0.1W; SizeArea_mm2: 1.28; AEC Qualified: N; VDC_V: 75V; AEC Category: Q200; SizeAreaWB_mm2: 4.68
R106 = CMP-0022900-4: RES, 1.00, 1%, 0.1 W, 0603; Manufacturer: Yageo; Power_W: 100mW; TempCo: 200 ppm/C; Value_Code: 1R00; Value: 1.00; EIA_Code: E96; Res_ohm: 1; SizeX_mm: 1.6; SizeY_mm: 0.8; Value2: 0.1W; SizeArea_mm2: 1.28; AEC Qualified: N; VDC_V: 75V; AEC Category: Q200; SizeAreaWB_mm2: 4.68
R107 = CMP-0022913-5: RES, 21.5 k, 1%, 0.1 W, 0603; Manufacturer: Yageo; Power_W: 100mW; TempCo: 100 ppm/C; Value_Code: 21k5; Value: 21.5k; EIA_Code: E96; SizeX_mm: 1.6; SizeY_mm: 0.8; SizeZ_mm: 1; Value2: 0.1W; SizeArea_mm2: 1.28; AEC Qualified: N; VDC_V: 75V; AEC Category: Q200; SizeAreaWB_mm2: 4.68
R108 = CMP-0096703-1: NTC Thermistor 470k 0603 (1608 Metric); Manufacturer: TDK; AEC Qualified: No; Res_ohm: 470kΩ; Power_W: 180mW; B 25 50: 4386K; B 25 100: 4480K; SizeZ_mm: 0.9mm; B 25 85: 4455K; B Tolerance: 3%; Tolerance_%: 5%
R109 R114 R115 = CMP-0020707-3: RES, 3.3 M, 5%, 0.125 W, AEC-Q200 Grade 0, 0805; Manufacturer: Panasonic; Power_W: 125mW; TempCo: 150 ppm/C; Value_Code: 3M30; Value: 3.3Meg; EIA_Code: E24; SizeX_mm: 2; SizeY_mm: 1.25; SizeZ_mm: 1.45; Value2: 0.125W; SizeArea_mm2: 2.5; AEC Qualified: Y; VDC_V: 150V; AEC Category: Q200; AEC Grade: 0; SizeAreaWB_mm2: 6.75
R110 = CMP-0023050-5: RES, 35.7 k, 1%, 0.1 W, 0603; Manufacturer: Yageo; Power_W: 100mW; TempCo: 100 ppm/C; Value_Code: 35k7; Value: 35.7k; EIA_Code: E96; SizeX_mm: 1.6; SizeY_mm: 0.8; SizeZ_mm: 1; Value2: 0.1W; SizeArea_mm2: 1.28; AEC Qualified: N; VDC_V: 75V; AEC Category: Q200; SizeAreaWB_mm2: 4.68
R111 = CMP-0022804-5: RES, 14.0 k, 1%, 0.1 W, 0603; Manufacturer: Yageo; Power_W: 100mW; TempCo: 100 ppm/C; Value_Code: 14k0; Value: 14.0k; EIA_Code: E96; Res_ohm: 14k; SizeX_mm: 1.6; SizeY_mm: 0.8; SizeZ_mm: 1; Value2: 0.1W; SizeArea_mm2: 1.28; AEC Qualified: N; VDC_V: 75V; AEC Category: Q200; SizeAreaWB_mm2: 4.68
R112 = CMP-0025886-5: RES, 10 k, 5%, 0.1 W, 0603; Manufacturer: Yageo; Power_W: 100mW; TempCo: 100 ppm/C; Value_Code: 10k0; Value: 10k; EIA_Code: E24; SizeX_mm: 1.6; SizeY_mm: 0.8; SizeZ_mm: 1; Value2: 0.1W; SizeArea_mm2: 1.28; AEC Qualified: N; VDC_V: 75V; AEC Category: Q200; SizeAreaWB_mm2: 4.68
R113 = CMP-0022051-5: RES, 143, 1%, 0.1 W, AEC-Q200 Grade 0, 0603; Manufacturer: Vishay-Dale; Power_W: 100mW; TempCo: 100 ppm/C; Value_Code: 143R; Value: 143; EIA_Code: E96; SizeX_mm: 1.6; SizeY_mm: 0.8; SizeZ_mm: 1; Value2: 0.1W; SizeArea_mm2: 1.28; AEC Qualified: Y; VDC_V: 75V; AEC Category: Q200; AEC Grade: 0
R116 = CMP-0022588-5: RES, 750, 1%, 0.1 W, AEC-Q200 Grade 0, 0603; Manufacturer: Vishay-Dale; Power_W: 100mW; TempCo: 100 ppm/C; Value_Code: 750R; Value: 750; EIA_Code: E96; SizeX_mm: 1.6; SizeY_mm: 0.8; SizeZ_mm: 1; Value2: 0.1W; SizeArea_mm2: 1.28; AEC Qualified: Y; VDC_V: 75V; AEC Category: Q200; AEC Grade: 0
R117 = CMP-0023142-5: RES, 49.9 k, 1%, 0.1 W, 0603; Manufacturer: Yageo; Power_W: 100mW; TempCo: 100 ppm/C; Value_Code: 49k9; Value: 49.9k; EIA_Code: E96; SizeX_mm: 1.6; SizeY_mm: 0.8; SizeZ_mm: 1; Value2: 0.1W; SizeArea_mm2: 1.28; AEC Qualified: N; VDC_V: 75V; AEC Category: Q200; SizeAreaWB_mm2: 4.68
R118 = CMP-0080488-1: RES, 10.0 k, 1%, 0.1 W, 0603; Manufacturer: TT Electronics/IRC; Power_W: 100mW; TempCo: 100 ppm/C; SizeAreaWB_mm2: 4.68; Value_Code: 10k0; Value: 10.0k; EIA_Code: E96; Res_ohm: 10k; SizeX_mm: 1.6; SizeY_mm: 0.8; SizeZ_mm: 1; Value2: 0.1W; SizeArea_mm2: 1.28; AEC Qualified: N; AEC Category: Q200
R119 = CMP-0023292-5: RES, 82.0 k, 1%, 0.1 W, 0603; Manufacturer: Yageo; Power_W: 100mW; TempCo: 100 ppm/C; Value_Code: 82k0; Value: 82.0k; Res_ohm: 82k; SizeX_mm: 1.6; SizeY_mm: 0.8; SizeZ_mm: 1; Value2: 0.1W; SizeArea_mm2: 1.28; AEC Qualified: N; VDC_V: 75V; AEC Category: Q200; SizeAreaWB_mm2: 4.68
R120 = CMP-0023226-4: RES, 649 k, 1%, 0.1 W, 0603; Manufacturer: Yageo; Power_W: 100mW; TempCo: 100 ppm/C; Value: 649k; EIA_Code: E96; SizeX_mm: 1.6; SizeY_mm: 0.8; SizeZ_mm: 1; Value2: 0.1W; SizeArea_mm2: 1.28; AEC Qualified: N; VDC_V: 75V; AEC Category: Q200; SizeAreaWB_mm2: 4.68
R121 = CMP-0023052-4: RES, 360 k, 1%, 0.1 W, 0603; Manufacturer: Yageo; Power_W: 100mW; TempCo: 100 ppm/C; Value: 360k; SizeX_mm: 1.6; SizeY_mm: 0.8; SizeZ_mm: 1; Value2: 0.1W; SizeArea_mm2: 1.28; AEC Qualified: N; VDC_V: 75V; AEC Category: Q200; SizeAreaWB_mm2: 4.68
R123 = CMP-0025821-4: RES, 4.7, 5%, 0.1 W, AEC-Q200 Grade 0, 0603; Manufacturer: Vishay-Dale; Power_W: 100mW; TempCo: 200 ppm/C; Value_Code: 4R70; Value: 4.7; EIA_Code: E24; SizeX_mm: 1.6; SizeY_mm: 0.8; SizeZ_mm: 1; Value2: 0.1W; SizeArea_mm2: 1.28; AEC Qualified: Y; VDC_V: 75V; AEC Category: Q200; AEC Grade: 0
R124 = CMP-0023201-5: RES, 5.49 k, 1%, 0.1 W, 0603; Manufacturer: Yageo; Power_W: 100mW; TempCo: 100 ppm/C; Value_Code: 5k49; Value: 5.49k; EIA_Code: E96; SizeX_mm: 1.6; SizeY_mm: 0.8; SizeZ_mm: 1; Value2: 0.1W; SizeArea_mm2: 1.28; AEC Qualified: N; VDC_V: 75V; AEC Category: Q200; SizeAreaWB_mm2: 4.68
R125 = CMP-0022919-4: RES, 221 k, 1%, 0.1 W, 0603; Manufacturer: Yageo; Power_W: 100mW; TempCo: 100 ppm/C; Value: 221k; EIA_Code: E96; SizeX_mm: 1.6; SizeY_mm: 0.8; SizeZ_mm: 1; Value2: 0.1W; SizeArea_mm2: 1.28; AEC Qualified: N; VDC_V: 75V; AEC Category: Q200; SizeAreaWB_mm2: 4.68
R126 = CMP-0025768-4: RES, 2.0 k, 5%, 0.1 W, AEC-Q200 Grade 0, 0603; Manufacturer: Vishay-Dale; Power_W: 100mW; TempCo: 200 ppm/C; Value_Code: 2k00; Value: 2.0k; EIA_Code: E24; Res_ohm: 2k; SizeX_mm: 1.6; SizeY_mm: 0.8; SizeZ_mm: 1; Value2: 0.1W; SizeArea_mm2: 1.28; AEC Qualified: Y; VDC_V: 75V; AEC Category: Q200; AEC Grade: 0
R127 = CMP-0022879-5: RES, 1.47 k, 1%, 0.1 W, 0603; Manufacturer: Yageo; Power_W: 100mW; TempCo: 100 ppm/C; Value_Code: 1k47; Value: 1.47k; EIA_Code: E96; SizeX_mm: 1.6; SizeY_mm: 0.8; SizeZ_mm: 1; Value2: 0.1W; SizeArea_mm2: 1.28; AEC Qualified: N; VDC_V: 75V; AEC Category: Q200; SizeAreaWB_mm2: 4.68
R128 R129 = CMP-0025712-4: RES, 12, 5%, 0.1 W, AEC-Q200 Grade 0, 0603; Manufacturer: Vishay-Dale; Power_W: 100mW; TempCo: 200 ppm/C; Value_Code: 12R0; Value: 12; EIA_Code: E24; SizeX_mm: 1.6; SizeY_mm: 0.8; SizeZ_mm: 1; Value2: 0.1W; SizeArea_mm2: 1.28; AEC Qualified: Y; VDC_V: 75V; AEC Category: Q200; AEC Grade: 0
R130 R131 = CMP-0025912-5: RES, 330, 5%, 0.1 W, 0603; Manufacturer: Yageo; Power_W: 100mW; TempCo: 100 ppm/C; Value_Code: 330R; Value: 330; EIA_Code: E24; SizeX_mm: 1.6; SizeY_mm: 0.8; SizeZ_mm: 1; Value2: 0.1W; SizeArea_mm2: 1.28; AEC Qualified: N; VDC_V: 75V; AEC Category: Q200; SizeAreaWB_mm2: 4.68
R132 = CMP-0022822-4: RES, 162 k, 1%, 0.1 W, 0603; Manufacturer: Yageo; Power_W: 100mW; TempCo: 100 ppm/C; Value: 162k; EIA_Code: E96; SizeX_mm: 1.6; SizeY_mm: 0.8; SizeZ_mm: 1; Value2: 0.1W; SizeArea_mm2: 1.28; AEC Qualified: N; VDC_V: 75V; AEC Category: Q200; SizeAreaWB_mm2: 4.68
T101 = XFRM_LLC
TP101-TP106 = CMP-0055148-1: as TP1 on sheet 240W_GaN_PFC_LLC_AC_EMI
U101 U103 = CMP-0121224-1: Power Switch/Driver 1:1 N-Channel 7.7A 38-VQFN (8x5.3); Manufacturer: Texas Instruments; Part Number: LMG3612REQR; SizeZ_mm: 1mm; AEC Qualified: No; Max Supply Voltage: 26V; Min Supply Voltage: 10V; Nominal Supply Current: 2.2mA; Number Of Outputs: 1; Standoff Height: 0mm; TJmax_C: +150°C
U102 = CMP-0095300-2: 750kHz Wide VIN/VOUT Range LLC Controller Optimized for Light Load Efficiency; Manufacturer: Texas Instruments; SizeZ_mm: 1.75mm; Number Of Outputs: 2; TaMin_C: -40°C; Standoff Height: 0.1mm; Max Supply Voltage: 18.5V; Switching Topology: Other; TJmax_C: +150°C; TaMax_C: +125°C; AEC Qualified: No; Switching Frequency: 30-750kHz; AEC Category: Q200; CompType: IC
U104 = CMP-0121574-1: Dual, 36-V 1.2-MHz low-offset-voltage operational amplifier with internal reference 8-SOIC -40 to 125; Manufacturer: Texas Instruments; SizeZ_mm: 1.75mm; AEC Qualified: No; Gain Bandwidth: 1.2MHz; Input Bias Current: -0.015uA; Input Offset Voltage: 0.3mV; Max Supply Voltage: 36V; Min Supply Voltage: 3V; Nominal Supply Current: 0.55mA; Number Of Channels: 2; Output Current Per Channel: 24mA; Standoff Height: 0.11mm; TaMax_C: +125°C; TaMin_C: -40°C; TJmax_C: +150°C; Voltage Gain: 210V/mV
U105 = CMP-0121571-1: Power Supply Controller Flyback, Forward Converters, LLC 8-SOIC; Manufacturer: Monolithic Power Systems; SizeZ_mm: 1.75mm; AEC Qualified: No; Max Power Dissipation: 1.4W; Max Supply Voltage: 35V; Min Supply Voltage: 4.2V; Nominal Supply Current: 4.6-16mA; Number Of Outputs: 2; Standoff Height: 0.1mm; TJmax_C: +125°C

## Sheet 240W_PFC_Stage.SchDoc
size 431 x 279 mm; Date: Not shown in title block; ApprovedBy: Not shown in title block; CheckedBy: Not shown in title block; Author: Not shown in title block; CompanyName: Not shown in title block; Engineer: Not shown in title block; Organization: Not shown in title block; Address1: Not shown in title block; Address2: Not shown in title block; Address3: Not shown in title block; Address4: Not shown in title block; DocumentNumber: 1; Revision: Use project parameter SCH_Rev; SheetNumber: 3; SheetTotal: 3; PageSetup: Record=PageOptions¦CenterHorizontal=True¦CenterVertical=True¦PrintScale=1.00¦XCorrection=1.00¦YCorrection=1.00¦PrintKind=0¦BorderSize=5000000¦LeftOffset=0¦BottomOffset=0¦Orientation=2¦PaperLength=1000¦PaperWidth=1000¦Scale=100¦PaperSource=15¦PrintQuality=600¦MediaType=1¦DitherType=10¦PaperKind=Letter¦PrintScaleMode=1
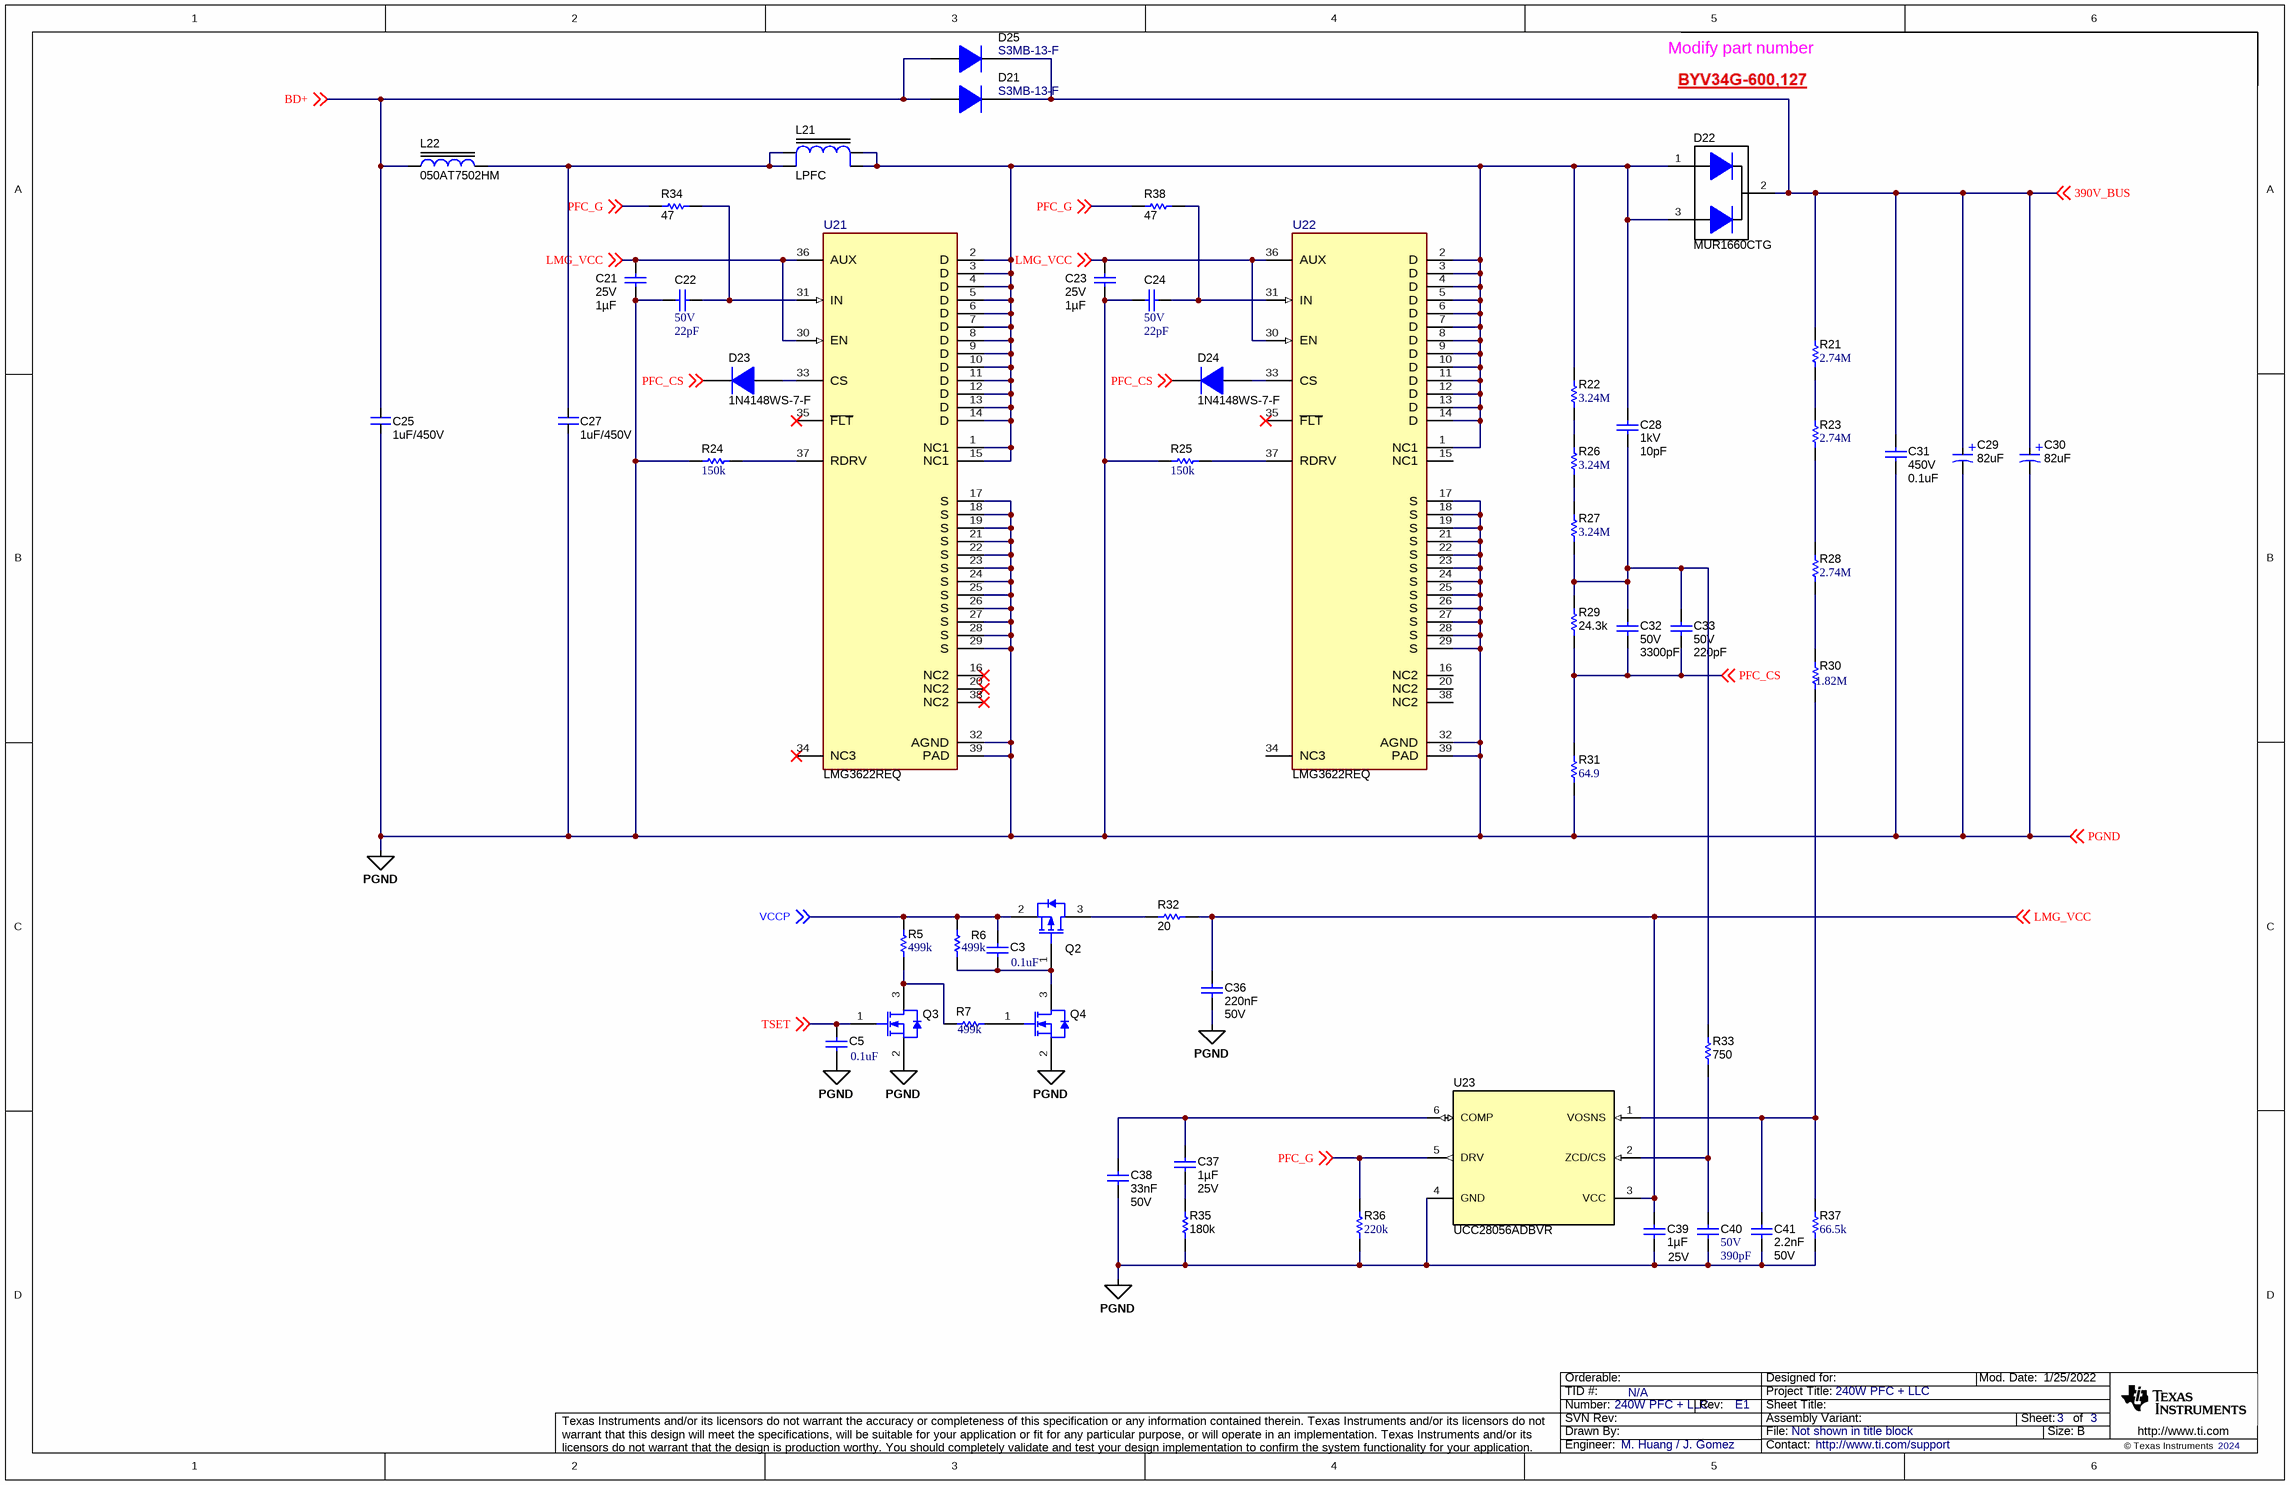
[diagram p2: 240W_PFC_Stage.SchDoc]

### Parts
C3  ValueDisplayed: 0.1uF  [0402]  (hidden comment: GRM155R61E104KA87D)
C5  ValueDisplayed: 0.1uF  [0402]  (hidden comment: GRM155R61E104KA87D)
C21  Cap_F: 1µF  VDC_V: 25V  [0603_HV]  (hidden comment: GRJ188R71E105KE11D)
C22  VDC_V: 50V  ValueDisplayed: 22pF  [0603_HV]  (hidden comment: CGA3E2C0G1H220J080AA)
C23  Cap_F: 1µF  VDC_V: 25V  [0603_HV]  (hidden comment: GRJ188R71E105KE11D)
C24  VDC_V: 50V  ValueDisplayed: 22pF  [0603_HV]  (hidden comment: CGA3E2C0G1H220J080AA)
C25  1uF/450V  [C_film_17.5x7]
C27  1uF/450V  [C_film_17.5x7]
C28  VDC_V: 1kV  ValueDisplayed: 10pF  [1206L]  (hidden comment: VJ1206A100JXGAT5Z)
C29  82uF  [Cap_12.5x40_H1]
C30  82uF  [Cap_12.5x40_H1]
C31  VDC_V: 450V  ValueDisplayed: 0.1uF  [1206_180]  (hidden comment: C3216X7T2W104K160AE)
C32  VDC_V: 50V  ValueDisplayed: 3300pF  [0603_HV]  (hidden comment: GRM1885C1H332JA01D)
C33  VDC_V: 50V  ValueDisplayed: 220pF  [0603_HV]  (hidden comment: GRM1885C1H221JA01D)
C36  Cap_F: 220nF  VDC_V: 50V  [0603_HV]  (hidden comment: GCM188R71H224KA64D)
C37  Cap_F: 1µF  VDC_V: 25V  [0603_HV]  (hidden comment: 06033C105KAT2A)
C38  Cap_F: 33nF  VDC_V: 50V  [0603_HV]  (hidden comment: GRM188R71H333KA61D)
C39  Cap_F: 1µF  VDC_V: 25V  [0603_HV]  (hidden comment: 06033C105KAT2A)
C40  VDC_V: 50V  ValueDisplayed: 390pF  [0603_HV]  (hidden comment: C0603C391J5GACTU)
C41  Cap_F: 2.2nF  VDC_V: 50V  [0603_HV]  (hidden comment: C0603C222K5RACTU)
D21  S3MB-13-F  [SMB]
D22  MUR1660CTG  [TO-220AB]
D23  1N4148WS-7-F  [SOD-323]
D24  1N4148WS-7-F  [SOD-323]
D25  S3MB-13-F  [SMB]
L21  LPFC  [EQ33]
L22  050AT7502HM  [L_Ring_H_D=16.76mm]
Q2  SI2309CDS-T1-E3  [SOT-23]  (value not drawn)
Q3  2N7002-7-F  [SOT-23]  (value not drawn)
Q4  2N7002-7-F  [SOT-23]  (value not drawn)
R5  ValueDisplayed: 499k  [0402]  (hidden comment: CRCW0402499KFKED)
R6  ValueDisplayed: 499k  [0402]  (hidden comment: CRCW0402499KFKED)
R7  ValueDisplayed: 499k  [0402]  (hidden comment: CRCW0402499KFKED)
R21  ValueDisplayed: 2.74M  [0805_HV]  (hidden comment: CRCW08052M74FKEA)
R22  ValueDisplayed: 3.24M  [0805_HV]  (hidden comment: CRCW08053M24FKEA)
R23  ValueDisplayed: 2.74M  [0805_HV]  (hidden comment: CRCW08052M74FKEA)
R24  ValueDisplayed: 150k  [0603_HV]  (hidden comment: CRCW0603150KJNEA)
R25  ValueDisplayed: 150k  [0603_HV]  (hidden comment: CRCW0603150KJNEA)
R26  ValueDisplayed: 3.24M  [0805_HV]  (hidden comment: CRCW08053M24FKEA)
R27  ValueDisplayed: 3.24M  [0805_HV]  (hidden comment: CRCW08053M24FKEA)
R28  ValueDisplayed: 2.74M  [0805_HV]  (hidden comment: CRCW08052M74FKEA)
R29  ValueDisplayed: 24.3k  [0603_HV]  (hidden comment: RC0603FR-0724K3L)
R30  ValueDisplayed: 1.82M  [0805_HV]  (hidden comment: CRCW08051M82FKEA)
R31  ValueDisplayed: 64.9  [0603]  (hidden comment: RC0603FR-0764R9L)
R32  ValueDisplayed: 20  [0603_HV]  (hidden comment: CRCW060320R0JNEA)
R33  ValueDisplayed: 750  [0603_HV]  (hidden comment: RC0603JR-07750RL)
R34  ValueDisplayed: 47  [0603_HV]  (hidden comment: CRCW060347R0JNEA)
R35  ValueDisplayed: 180k  [0603_HV]  (hidden comment: CRCW0603180KJNEA)
R36  ValueDisplayed: 220k  [0603_HV]  (hidden comment: CRCW0603220KJNEA)
R37  ValueDisplayed: 66.5k  [0603]  (hidden comment: RC0603FR-0766K5L)
R38  ValueDisplayed: 47  [0603_HV]  (hidden comment: CRCW060347R0JNEA)
U21  LMG3622REQ  [REQ0038A-MFG]
U22  LMG3622REQ  [REQ0038A-MFG]
U23  UCC28056ADBVR  [DBV0006A_N]

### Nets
PGND: C5.2 C21.1 C22.2 C23.1 C24.2 C25.2 C27.2 C29.2(N) C30.2(N) C31.2 C36.2 C38.2 C39.2 C40.2 C41.2 Q3.2(S) Q4.2(S) R24.1 R25.1 R31.1 R35.1 R36.1 R37.1 U21.17(S) U21.18(S) U21.19(S) U21.21(S) U21.22(S) U21.23(S) U21.24(S) U21.25(S) U21.26(S) U21.27(S) U21.28(S) U21.29(S) U21.32(AGND) U21.39(PAD) U22.17(S) U22.18(S) U22.19(S) U22.21(S) U22.22(S) U22.23(S) U22.24(S) U22.25(S) U22.26(S) U22.27(S) U22.28(S) U22.29(S) U22.32(AGND) U22.39(PAD) U23.4(GND) ; off-sheet PGND
390V_BUS: C29.1(P) C30.1(P) C31.1 D21.1(K) D22.2(K) D25.1(K) R21.2 ; off-sheet 390V_BUS
BD+: C25.1 D21.2(A) D25.2(A) L22.1 ; off-sheet BD+
LMG_VCC: C21.2 C23.2 C36.1 C39.1 R32.1 U21.30(EN) U21.36(AUX) U22.30(EN) U22.36(AUX) U23.3(VCC) ; off-sheet LMG_VCC
PFC_CS: C32.2 C33.2 D23.1(K) D24.1(K) R29.1 R31.2 ; off-sheet PFC_CS
PFC_G: R34.1 R36.2 R38.2 U23.5(DRV) ; off-sheet PFC_G
TSET: C5.1 Q3.1(G) ; off-sheet TSET
VCCP: C3.1 Q2.2(S) R5.2 R6.2 ; off-sheet VCCP
NetC3_2: C3.2 Q2.1(G) Q4.3(D) R6.1
NetC22_1: C22.1 R34.2 U21.31(IN)
NetC24_1: C24.1 R38.1 U22.31(IN)
NetC27_1: C27.1 L21.1 L21.2 L22.2
NetC28_1: C28.1 D22.1(A) D22.3(A) L21.4 L21.5 R22.2 U21.1(NC1) U21.2(D) U21.3(D) U21.4(D) U21.5(D) U21.6(D) U21.7(D) U21.8(D) U21.9(D) U21.10(D) U21.11(D) U21.12(D) U21.13(D) U21.14(D) U21.15(NC1) U22.1(NC1) U22.2(D) U22.3(D) U22.4(D) U22.5(D) U22.6(D) U22.7(D) U22.8(D) U22.9(D) U22.10(D) U22.11(D) U22.12(D) U22.13(D) U22.14(D)
NetC28_2: C28.2 C32.1 C33.1 R27.1 R29.2 R33.2
NetC37_1: C37.1 C38.1 U23.6(COMP)
NetC37_2: C37.2 R35.2
NetC40_1: C40.1 R33.1 U23.2(ZCD/CS)
NetC41_1: C41.1 R30.1 R37.2 U23.1(VOSNS)
NetD23_2: D23.2(A) U21.33(CS)
NetD24_2: D24.2(A) U22.33(CS)
NetQ2_3: Q2.3(D) R32.2
NetQ3_3: Q3.3(D) R5.1 R7.2
NetQ4_1: Q4.1(G) R7.1
NetR21_1: R21.1 R23.2
NetR22_1: R22.1 R26.2
NetR23_1: R23.1 R28.2
NetR24_2: R24.2 U21.37(RDRV)
NetR25_2: R25.2 U22.37(RDRV)
NetR26_1: R26.1 R27.2
NetR28_1: R28.1 R30.2

Not connected (* = marked no-connect by the designer): U21 16(NC2)* 20(NC2)* 34(NC3)* 35(~{FLT})* 38(NC2)*; U22 15(NC1) 16(NC2) 20(NC2) 34(NC3) 35(~{FLT})* 38(NC2)

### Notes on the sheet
- Modify part number

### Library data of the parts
C3 C5 = CMP-0006607-2: CAP, CERM, 0.1 uF, 25 V, +/- 10%, X5R, 0402; Manufacturer: MuRata; TaMin_C: -55°C; Polarized: N; SizeAreaWB_mm2: 3; Value1: Unknown; U/M: EA; Value: 0.1uF; TaMax_C: 85°C; SizeZ_mm: 0.6; SizeX_mm: 1; SizeY_mm: 0.5; Value2: 25V; Cap_F: 100nF; AEC Category: Q200
C21 C23 = CMP-0079720-1: as C117 on sheet 240W_LLC_Stage
C22 C24 = CMP-0007071-4: as C102 on sheet 240W_LLC_Stage
C25 C27 = C_film: Manufacturer: Used in BOM report; CompType: Used in some BOM reports.  Useful for finding later.
C28 = CMP-0009029-2: CAP, CERM, 10 pF, 1000 V, +/- 5%, C0G/NP0, 1206; Manufacturer: Vishay-Vitramon; TaMin_C: -55°C; Polarized: N; SizeAreaWB_mm2: 10.92; Value1: Unknown; U/M: EA; Value: 10pF; TaMax_C: 125°C; SizeZ_mm: 1.35; SizeX_mm: 3.2; SizeY_mm: 1.6; Cap_Case: 1206; Value2: 1000V; SizeArea_mm2: 5.12; AEC Category: Q200
C29 C30 = E-Cap: Manufacturer: Used in BOM report; CompType: Used in some BOM reports.  Useful for finding later.
C31 = CMP-0008728-1: CAP, CERM, 0.1 uF, 450 V, +/- 10%, X7T, 1206; Manufacturer: TDK; TaMin_C: -55°C; Polarized: N; SizeAreaWB_mm2: 10.92; Value1: Unknown; U/M: EA; Value: 0.1uF; TaMax_C: 125°C; SizeZ_mm: 1.8; SizeX_mm: 3.2; SizeY_mm: 1.6; Cap_Case: 1206; SizeArea_mm2: 5.12; Cap_F: 100nF; AEC Category: Q200
C32 = CMP-0007210-1: CAP, CERM, 3300 pF, 50 V, +/- 5%, C0G/NP0, 0603; Manufacturer: MuRata; TaMin_C: -55°C; Polarized: N; SizeAreaWB_mm2: 4.68; Value1: Unknown; U/M: EA; Value: 3300pF; TaMax_C: 125°C; SizeZ_mm: 1; SizeX_mm: 1.6; SizeY_mm: 0.8; Cap_Case: 0603; SizeArea_mm2: 1.28; Cap_F: 3.3nF; AEC Category: Q200
C33 = CMP-0007197-4: CAP, CERM, 220 pF, 50 V, +/- 5%, C0G/NP0, 0603; Manufacturer: MuRata; TaMin_C: -55°C; Polarized: N; SizeAreaWB_mm2: 4.68; Value1: Unknown; U/M: EA; Value: 220pF; TaMax_C: 125°C; SizeZ_mm: 1; SizeX_mm: 1.6; SizeY_mm: 0.8; Cap_Case: 0603; SizeArea_mm2: 1.28; AEC Category: Q200
C36 = CMP-0007145-3: CAP, CERM, 0.22 uF, 50 V, +/- 10%, X7R, AEC-Q200 Grade 1, 0603; Manufacturer: MuRata; TaMin_C: -55°C; Polarized: N; SizeAreaWB_mm2: 4.68; Value1: Unknown; U/M: EA; Value: 0.22uF; TaMax_C: 125°C; SizeZ_mm: 1; SizeX_mm: 1.6; SizeY_mm: 0.8; Cap_Case: 0603; SizeArea_mm2: 1.28; AEC Qualified: Y; AEC Category: Q200
C37 C39 = CMP-0006754-4: CAP, CERM, 1 uF, 25 V, +/- 10%, X7R, 0603; Manufacturer: AVX; TaMin_C: -55°C; Polarized: N; SizeAreaWB_mm2: 4.68; Value1: Unknown; U/M: EA; Value: 1uF; TaMax_C: 125°C; SizeZ_mm: 1; SizeX_mm: 1.6; SizeY_mm: 0.8; Cap_Case: 0603; SizeArea_mm2: 1.28; AEC Category: Q200
C38 = CMP-0007451-3: CAP, CERM, 0.033 uF, 50 V, +/- 10%, X7R, 0603; Manufacturer: MuRata; TaMin_C: -55°C; Polarized: N; SizeAreaWB_mm2: 4.68; Value1: Unknown; U/M: EA; TaMax_C: 125°C; SizeZ_mm: 1; SizeX_mm: 1.6; SizeY_mm: 0.8; Cap_Case: 0603; SizeArea_mm2: 1.28; AEC Category: Q200
C40 = CMP-0006932-4: CAP, CERM, 390 pF, 50 V, +/- 5%, C0G/NP0, 0603; Manufacturer: Kemet; TaMin_C: -55°C; Polarized: N; SizeAreaWB_mm2: 4.68; Value1: Unknown; U/M: EA; Value: 390pF; TaMax_C: 125°C; SizeZ_mm: 1; SizeX_mm: 1.6; SizeY_mm: 0.8; Cap_Case: 0603; SizeArea_mm2: 1.28; AEC Category: Q200
C41 = CMP-0006898-4: CAP, CERM, 2200 pF, 50 V, +/- 10%, X7R, 0603; Manufacturer: Kemet; TaMin_C: -55°C; Polarized: N; SizeAreaWB_mm2: 4.68; Value1: Unknown; U/M: EA; Value: 2200pF; TaMax_C: 125°C; SizeZ_mm: 1; SizeX_mm: 1.6; SizeY_mm: 0.8; Cap_Case: 0603; SizeArea_mm2: 1.28; AEC Category: Q200
D21 D25 = CMP-0077014-1: Diode, GP, 1000V, 3 A, SMB; Manufacturer: Diodes Incorporated; SizeAreaWB_mm2: 44.156; SizeArea_mm2: 21.336; TJmax_C: 175°C; AEC Category: Q101; SizeZ_mm: 2.6; Green_REACh: Incomplete; Io_A: 3A; Vf_V: 1.3V; SizeY_mm: 3.81; Green_Lifecycle: Not Set; U/M: EA; SizeX_mm: 5.6; Type: Ultrafast
D22 = CMP-0085337-1: Diode, Ultrafast, 600 V, 8 A, TO-220AB; Manufacturer: ON Semiconductor; AEC Qualified: N; AEC Category: Q101; SizeAreaWB_mm2: 79.3; Vr_V: 600V; SizeArea_mm2: 45.9; TJmax_C: 175°C; Value2: 16V; SizeY_mm: 4.5; RJC_CperW: 2; SizeX_mm: 10.2; Value: 600V; Io_A: 8A; SizeZ_mm: 19.4
D23 D24 = CMP-0079597-2: Diode, Switching, 75 V, 0.15 A, AEC-Q101, SOD-323; Manufacturer: Diodes Inc.; SizeX_mm: 2.7; Vf_V: 1.25V; AEC Qualified: Y; SizeArea_mm2: 3.645; AEC Category: Q101; SizeAreaWB_mm2: 8.695; Io_A: 150mA; SizeZ_mm: 1; Value1: 0.15A; SizeY_mm: 1.35; TJmax_C: 150°C; Vr_V: 75V; Value: 75V
L21 = L_FIX_more pins: Manufacturer: Used in BOM report; CompType: Used in some BOM reports.  Useful for finding later.
L22 = L_FIX: as L101 on sheet 240W_LLC_Stage
Q2 = CMP-0000090-3: MOSFET, P-CH, -60 V, -1.6 A, SOT-23; Alternate Manufacturer: None; Manufacturer: Vishay-Siliconix; SizeY_mm: 3; Value1: 0.4; SizeZ_mm: 1.1; SizeArea_mm2: 7.5; SizeX_mm: 2.5; Rdson45_ohm: 0.45; SizeAreaWB_mm2: 14; ChType: P; ChMode: Enhancement; IdsMax_A: -1.6A; VdsMax_V: -60V; AEC Category: Q101; Value2: 2.7 nC; Vgs_V: -20V; Value: -60V; QgTyp_nC: 2.7
Q3 Q4 = CMP-0000769-1: MOSFET, N-CH, 60 V, 0.17 A, SOT-23; Alternate Manufacturer: None; Manufacturer: Diodes Inc.; SizeZ_mm: 1.1; ChType: N; Value2: 223 nC; Value1: 7; VdsMax_V: 60V; SizeX_mm: 2.5; SizeY_mm: 3; Vgs_V: 20V; Value: 60V; Rdson45_ohm: 7.5; AEC Category: Q101; IdsMax_A: 1.7dA; SizeAreaWB_mm2: 14; U/M: EA; QgTyp_nC: 223
R5-R7 = CMP-0026401-2: RES, 499 k, 1%, 0.063 W, AEC-Q200 Grade 0, 0402; Manufacturer: Vishay-Dale; Power_W: 63mW; TempCo: 100 ppm/C; Value: 499k; EIA_Code: E96; SizeX_mm: 1; SizeY_mm: 0.5; SizeZ_mm: 0.6; Value2: 0.063W; AEC Qualified: Y; VDC_V: 50V; AEC Category: Q200; AEC Grade: 0
R21 R23 R28 = CMP-0021137-3: RES, 2.74 M, 1%, 0.125 W, AEC-Q200 Grade 0, 0805; Manufacturer: Vishay-Dale; Power_W: 125mW; TempCo: 100 ppm/C; Value_Code: 2M74; Value: 2.74Meg; EIA_Code: E96; SizeX_mm: 2; SizeY_mm: 1.25; SizeZ_mm: 1.45; Value2: 0.125W; SizeArea_mm2: 2.5; AEC Qualified: Y; VDC_V: 150V; AEC Category: Q200; AEC Grade: 0
R22 R26 R27 = CMP-0021222-4: RES, 3.24 M, 1%, 0.125 W, AEC-Q200 Grade 0, 0805; Manufacturer: Vishay-Dale; Power_W: 125mW; TempCo: 100 ppm/C; Value_Code: 3M24; Value: 3.24Meg; EIA_Code: E96; SizeX_mm: 2; SizeY_mm: 1.25; SizeZ_mm: 1.45; Value2: 0.125W; SizeArea_mm2: 2.5; AEC Qualified: Y; VDC_V: 150V; AEC Category: Q200; AEC Grade: 0
R24 R25 = CMP-0025717-4: as R101 on sheet 240W_LLC_Stage
R29 = CMP-0022943-5: RES, 24.3 k, 1%, 0.1 W, 0603; Manufacturer: Yageo; Power_W: 100mW; TempCo: 100 ppm/C; Value_Code: 24k3; Value: 24.3k; EIA_Code: E96; SizeX_mm: 1.6; SizeY_mm: 0.8; SizeZ_mm: 1; Value2: 0.1W; SizeArea_mm2: 1.28; AEC Qualified: N; VDC_V: 75V; AEC Category: Q200; SizeAreaWB_mm2: 4.68
R30 = CMP-0021005-3: RES, 1.82 M, 1%, 0.125 W, AEC-Q200 Grade 0, 0805; Manufacturer: Vishay-Dale; Power_W: 125mW; TempCo: 100 ppm/C; Value_Code: 1M82; Value: 1.82Meg; EIA_Code: E96; SizeX_mm: 2; SizeY_mm: 1.25; SizeZ_mm: 1.45; Value2: 0.125W; SizeArea_mm2: 2.5; AEC Qualified: Y; VDC_V: 150V; AEC Category: Q200; AEC Grade: 0
R31 = CMP-0023229-5: RES, 64.9, 1%, 0.1 W, 0603; Manufacturer: Yageo; Power_W: 100mW; TempCo: 100 ppm/C; Value_Code: 64R9; Value: 64.9; EIA_Code: E96; SizeX_mm: 1.6; SizeY_mm: 0.8; SizeZ_mm: 1; Value2: 0.1W; SizeArea_mm2: 1.28; AEC Qualified: N; VDC_V: 75V; AEC Category: Q200; SizeAreaWB_mm2: 4.68
R32 = CMP-0025754-1: RES, 20, 5%, 0.1 W, 0603; Manufacturer: Vishay-Dale; Power_W: 100mW; TempCo: 200 ppm/C; Value_Code: 20R0; U/M: EA; Value: 20; EIA_Code: E24; SizeX_mm: 1.6; SizeY_mm: 0.8; SizeZ_mm: 1; Value2: 0.1W; SizeArea_mm2: 1.28; VDC_V: 75V; AEC Category: Q200
R33 = CMP-0025939-5: RES, 750, 5%, 0.1 W, 0603; Manufacturer: Yageo; Power_W: 100mW; TempCo: 100 ppm/C; Value_Code: 750R; Value: 750; EIA_Code: E24; SizeX_mm: 1.6; SizeY_mm: 0.8; SizeZ_mm: 1; Value2: 0.1W; SizeArea_mm2: 1.28; AEC Qualified: N; VDC_V: 75V; AEC Category: Q200; SizeAreaWB_mm2: 4.68
R34 R38 = CMP-0025815-4: RES, 47, 5%, 0.1 W, AEC-Q200 Grade 0, 0603; Manufacturer: Vishay-Dale; Power_W: 100mW; TempCo: 200 ppm/C; Value_Code: 47R0; Value: 47; EIA_Code: E24; SizeX_mm: 1.6; SizeY_mm: 0.8; SizeZ_mm: 1; Value2: 0.1W; SizeArea_mm2: 1.28; AEC Qualified: Y; VDC_V: 75V; AEC Category: Q200; AEC Grade: 0
R35 = CMP-0025725-2: RES, 180 k, 5%, 0.1 W, 0603; Manufacturer: Vishay-Dale; Power_W: 100mW; TempCo: 200 ppm/C; U/M: EA; Value: 180k; EIA_Code: E24; SizeX_mm: 1.6; SizeY_mm: 0.8; SizeZ_mm: 1; Value2: 0.1W; SizeArea_mm2: 1.28; VDC_V: 75V; AEC Category: Q200
R36 = CMP-0025755-4: RES, 220 k, 5%, 0.1 W, AEC-Q200 Grade 0, 0603; Manufacturer: Vishay-Dale; Power_W: 100mW; TempCo: 200 ppm/C; Value: 220k; EIA_Code: E24; SizeX_mm: 1.6; SizeY_mm: 0.8; SizeZ_mm: 1; Value2: 0.1W; SizeArea_mm2: 1.28; AEC Qualified: Y; VDC_V: 75V; AEC Category: Q200; AEC Grade: 0
R37 = CMP-0023232-5: RES, 66.5 k, 1%, 0.1 W, 0603; Manufacturer: Yageo; Power_W: 100mW; TempCo: 100 ppm/C; Value_Code: 66k5; Value: 66.5k; EIA_Code: E96; SizeZ_mm: 1; Value2: 0.1W; SizeArea_mm2: 1.28; AEC Qualified: N; VDC_V: 75V; AEC Category: Q200; SizeAreaWB_mm2: 4.68; SizeX_mm: 1.6; SizeY_mm: 0.8
U21 U22 = CMP-0096535-2: 650-V GaN FET With Integrated Driver and Current Sense Emulation; Manufacturer: Texas Instruments; Number Of Drivers: 1; CompType: IC; Max Supply Voltage: 26V; SizeZ_mm: 1mm; AEC Category: Q200; Min Supply Voltage: 10V; AEC Qualified: No; TJmax_C: +175°C; Standoff Height: 0mm
U23 = CMP-0860501-1: 6-Pin Single-Phase Transition-Mode PFC Controller, DBV0006A (SOT-23-6); Alternate Manufacturer: Texas Instruments; SizeY_mm: 2.9; SizeAreaWB_mm2: 14.82; AEC Category: Q200; SizeX_mm: 2.8; Rating: Catalog; SizeArea_mm2: 8.12; CompType: IC; SizeZ_mm: 1.45; AEC Qualified: N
